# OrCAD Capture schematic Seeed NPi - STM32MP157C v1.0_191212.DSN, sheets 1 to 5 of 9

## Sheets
1 03 1000M Ethernet: size A3; rev: v1.01
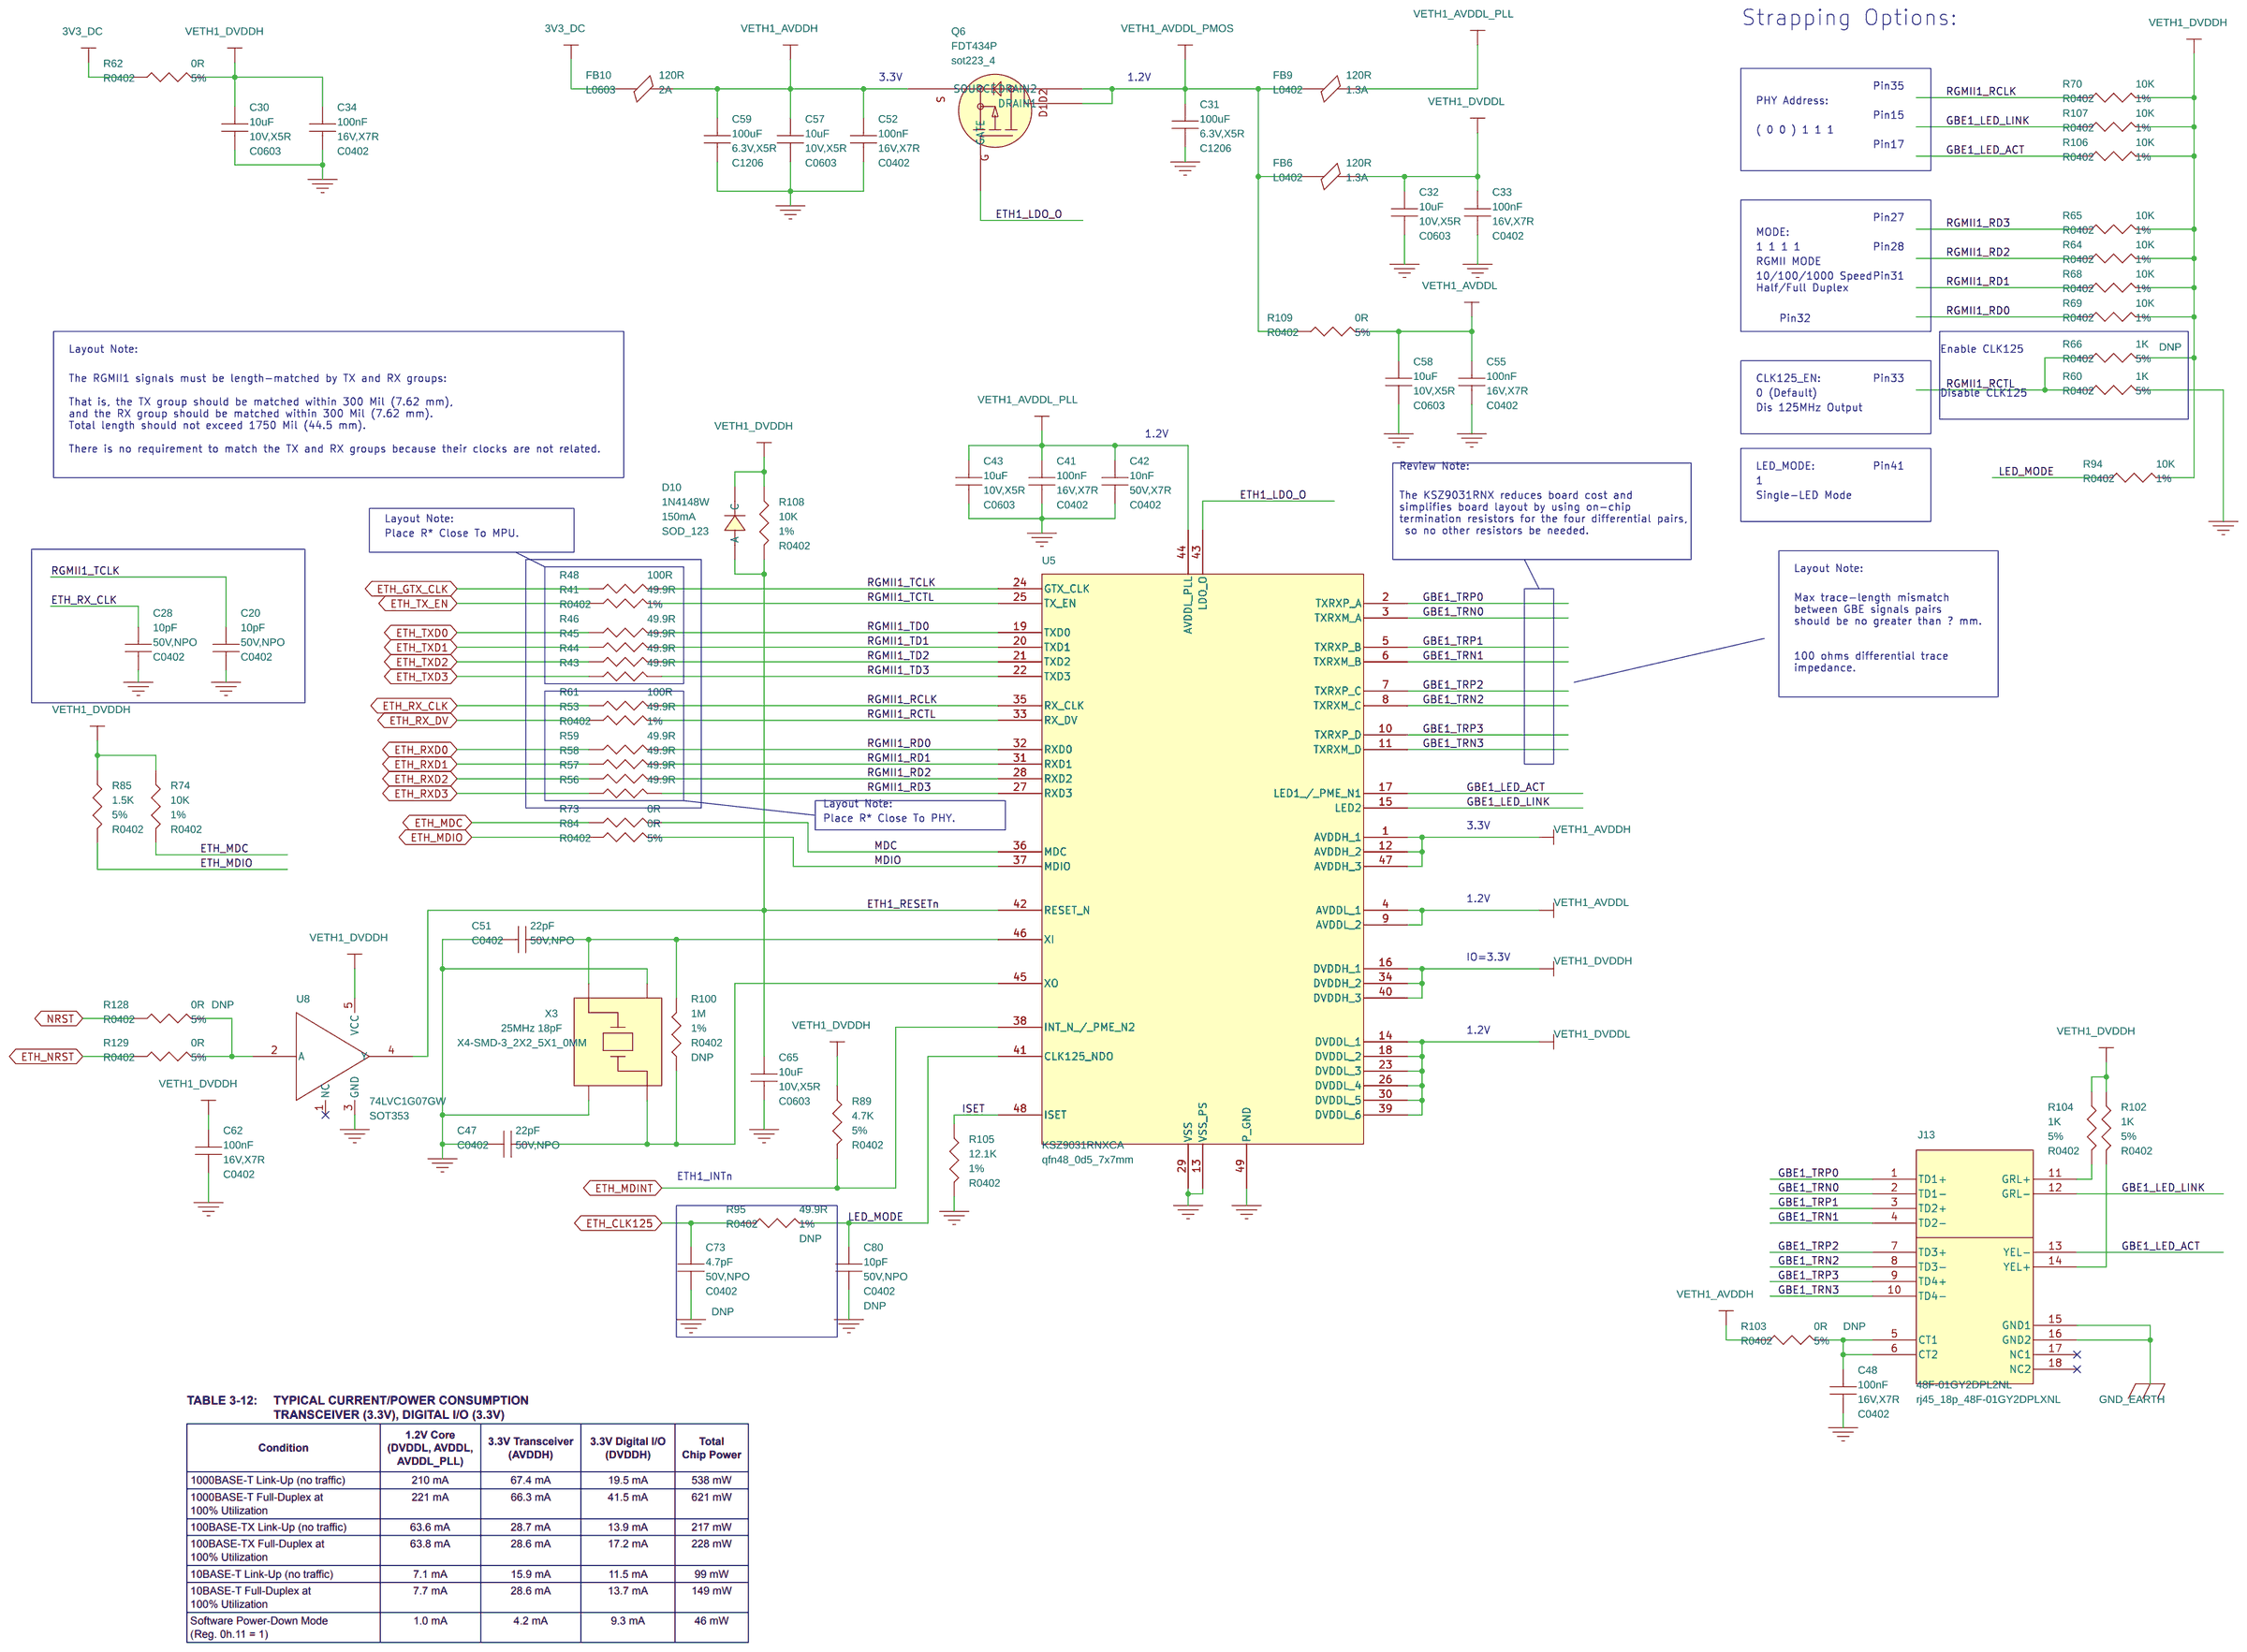
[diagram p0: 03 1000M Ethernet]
2 02 POWER: size A3
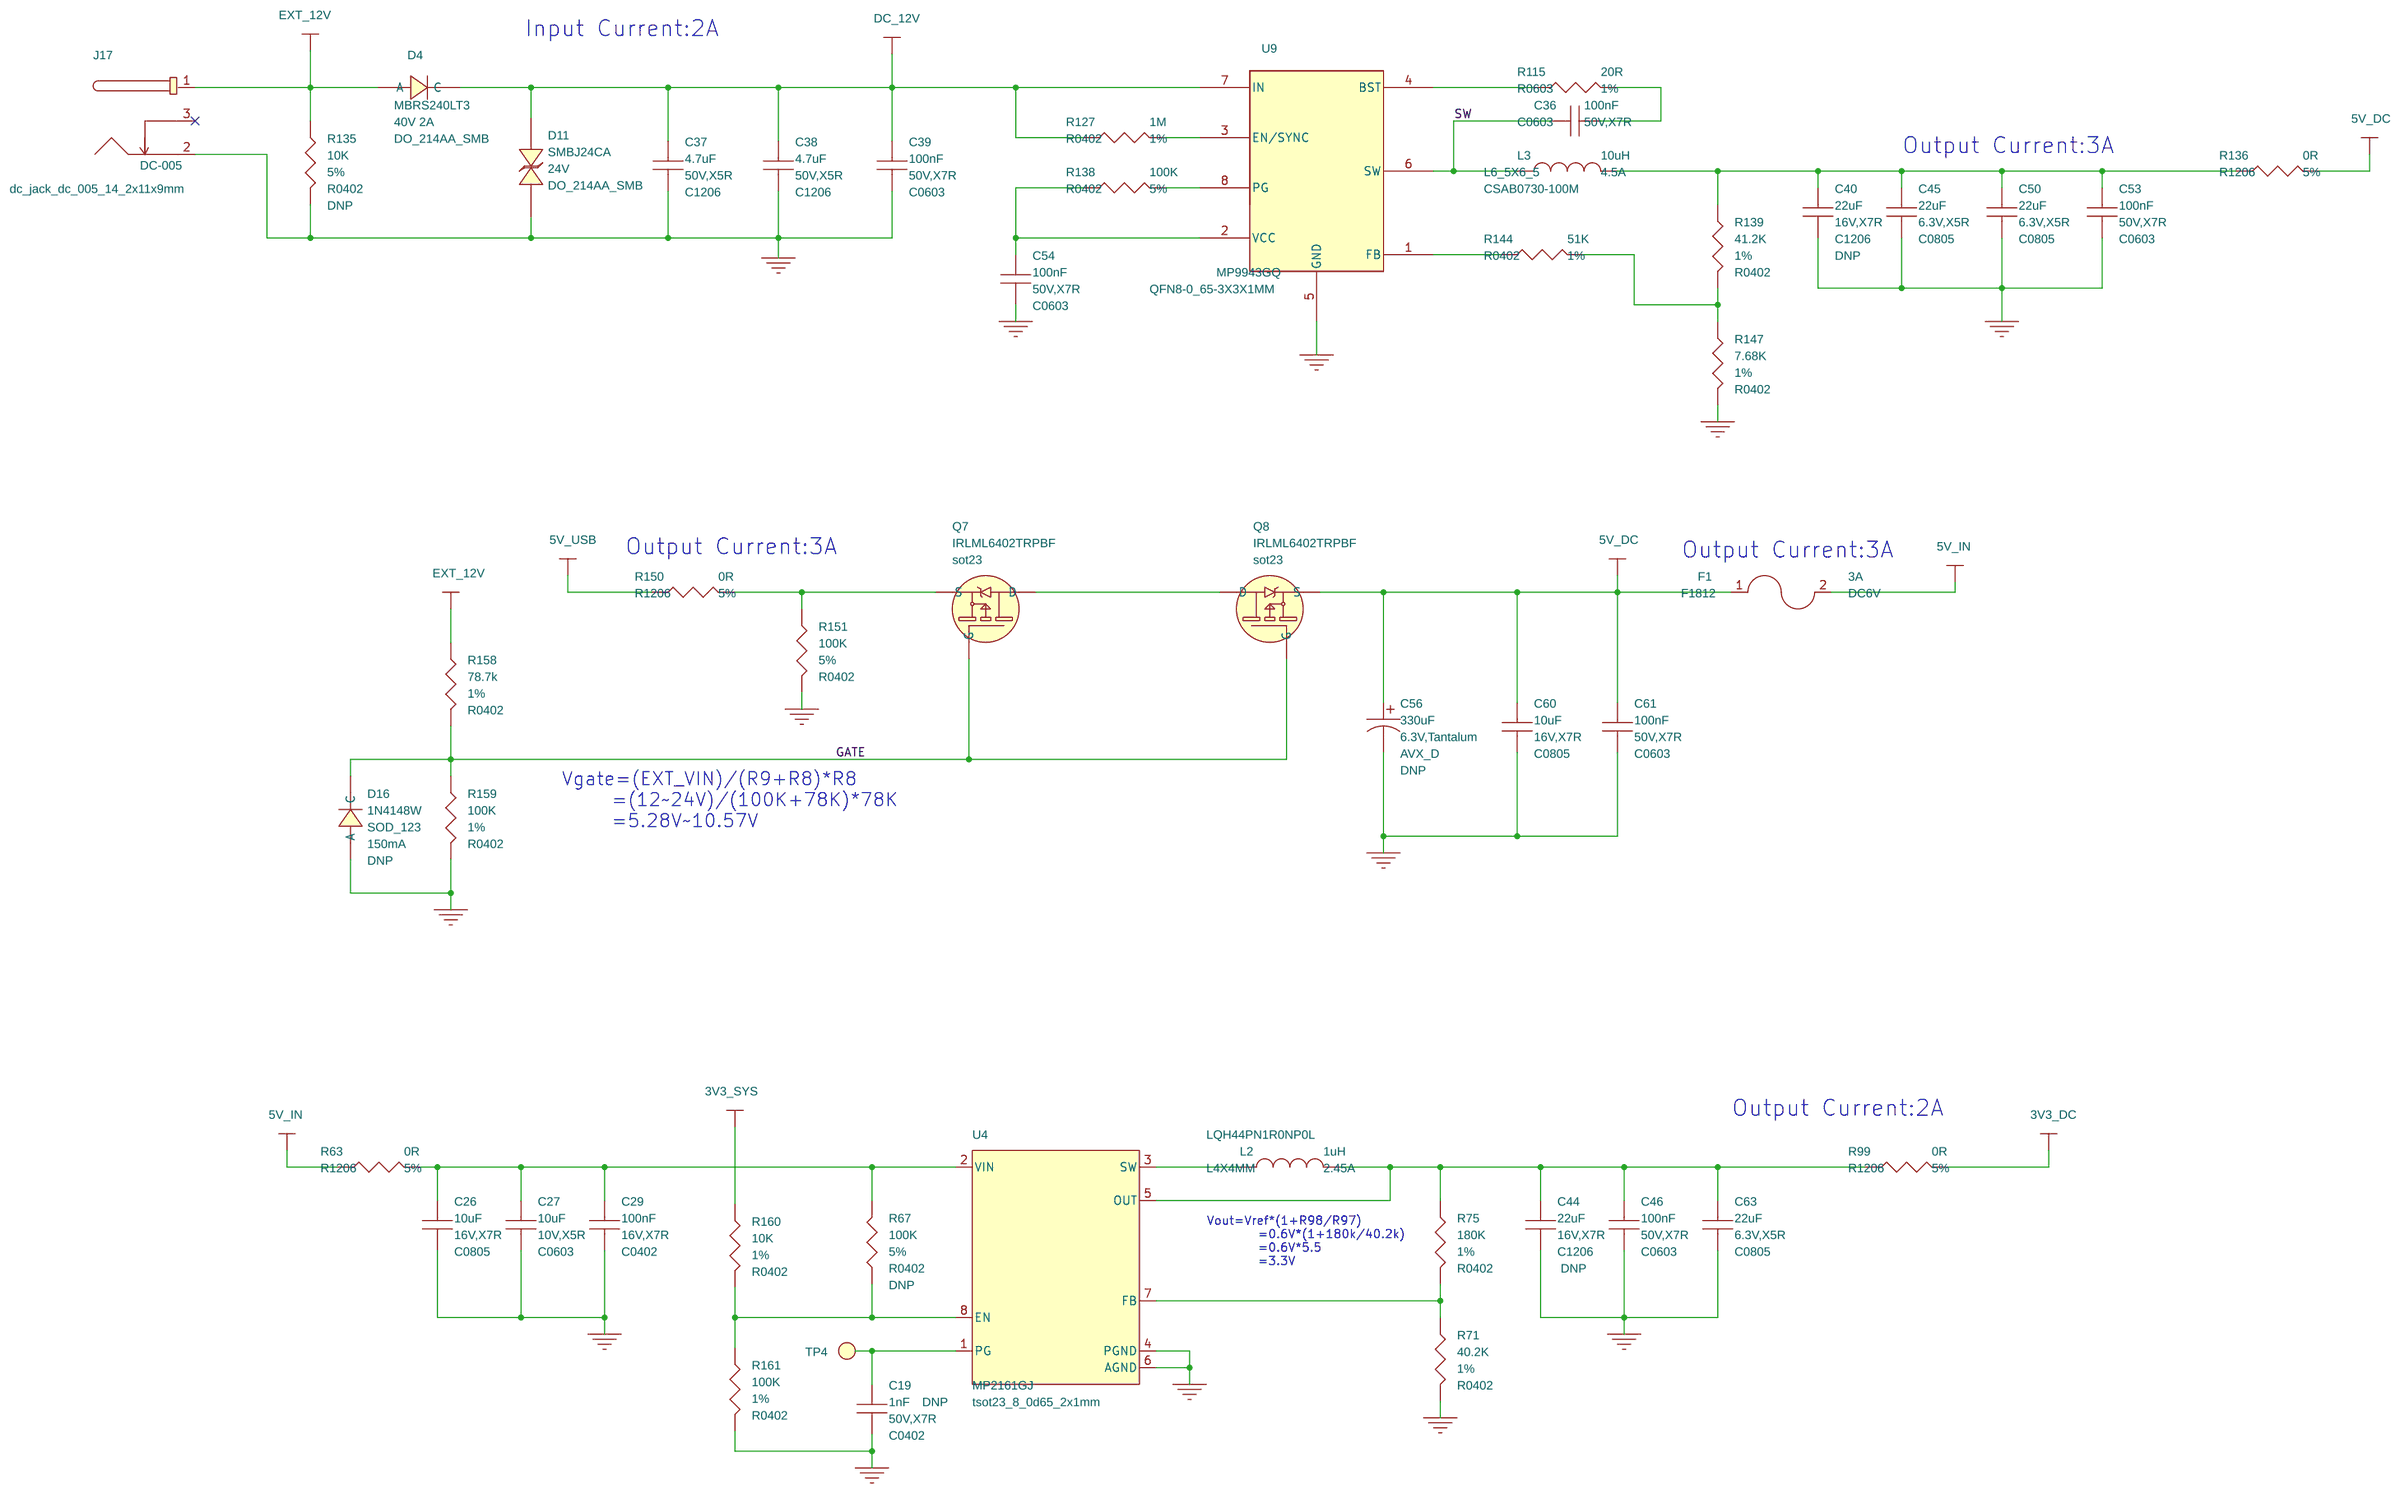
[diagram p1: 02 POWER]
3 07 PIN NAME: size A3
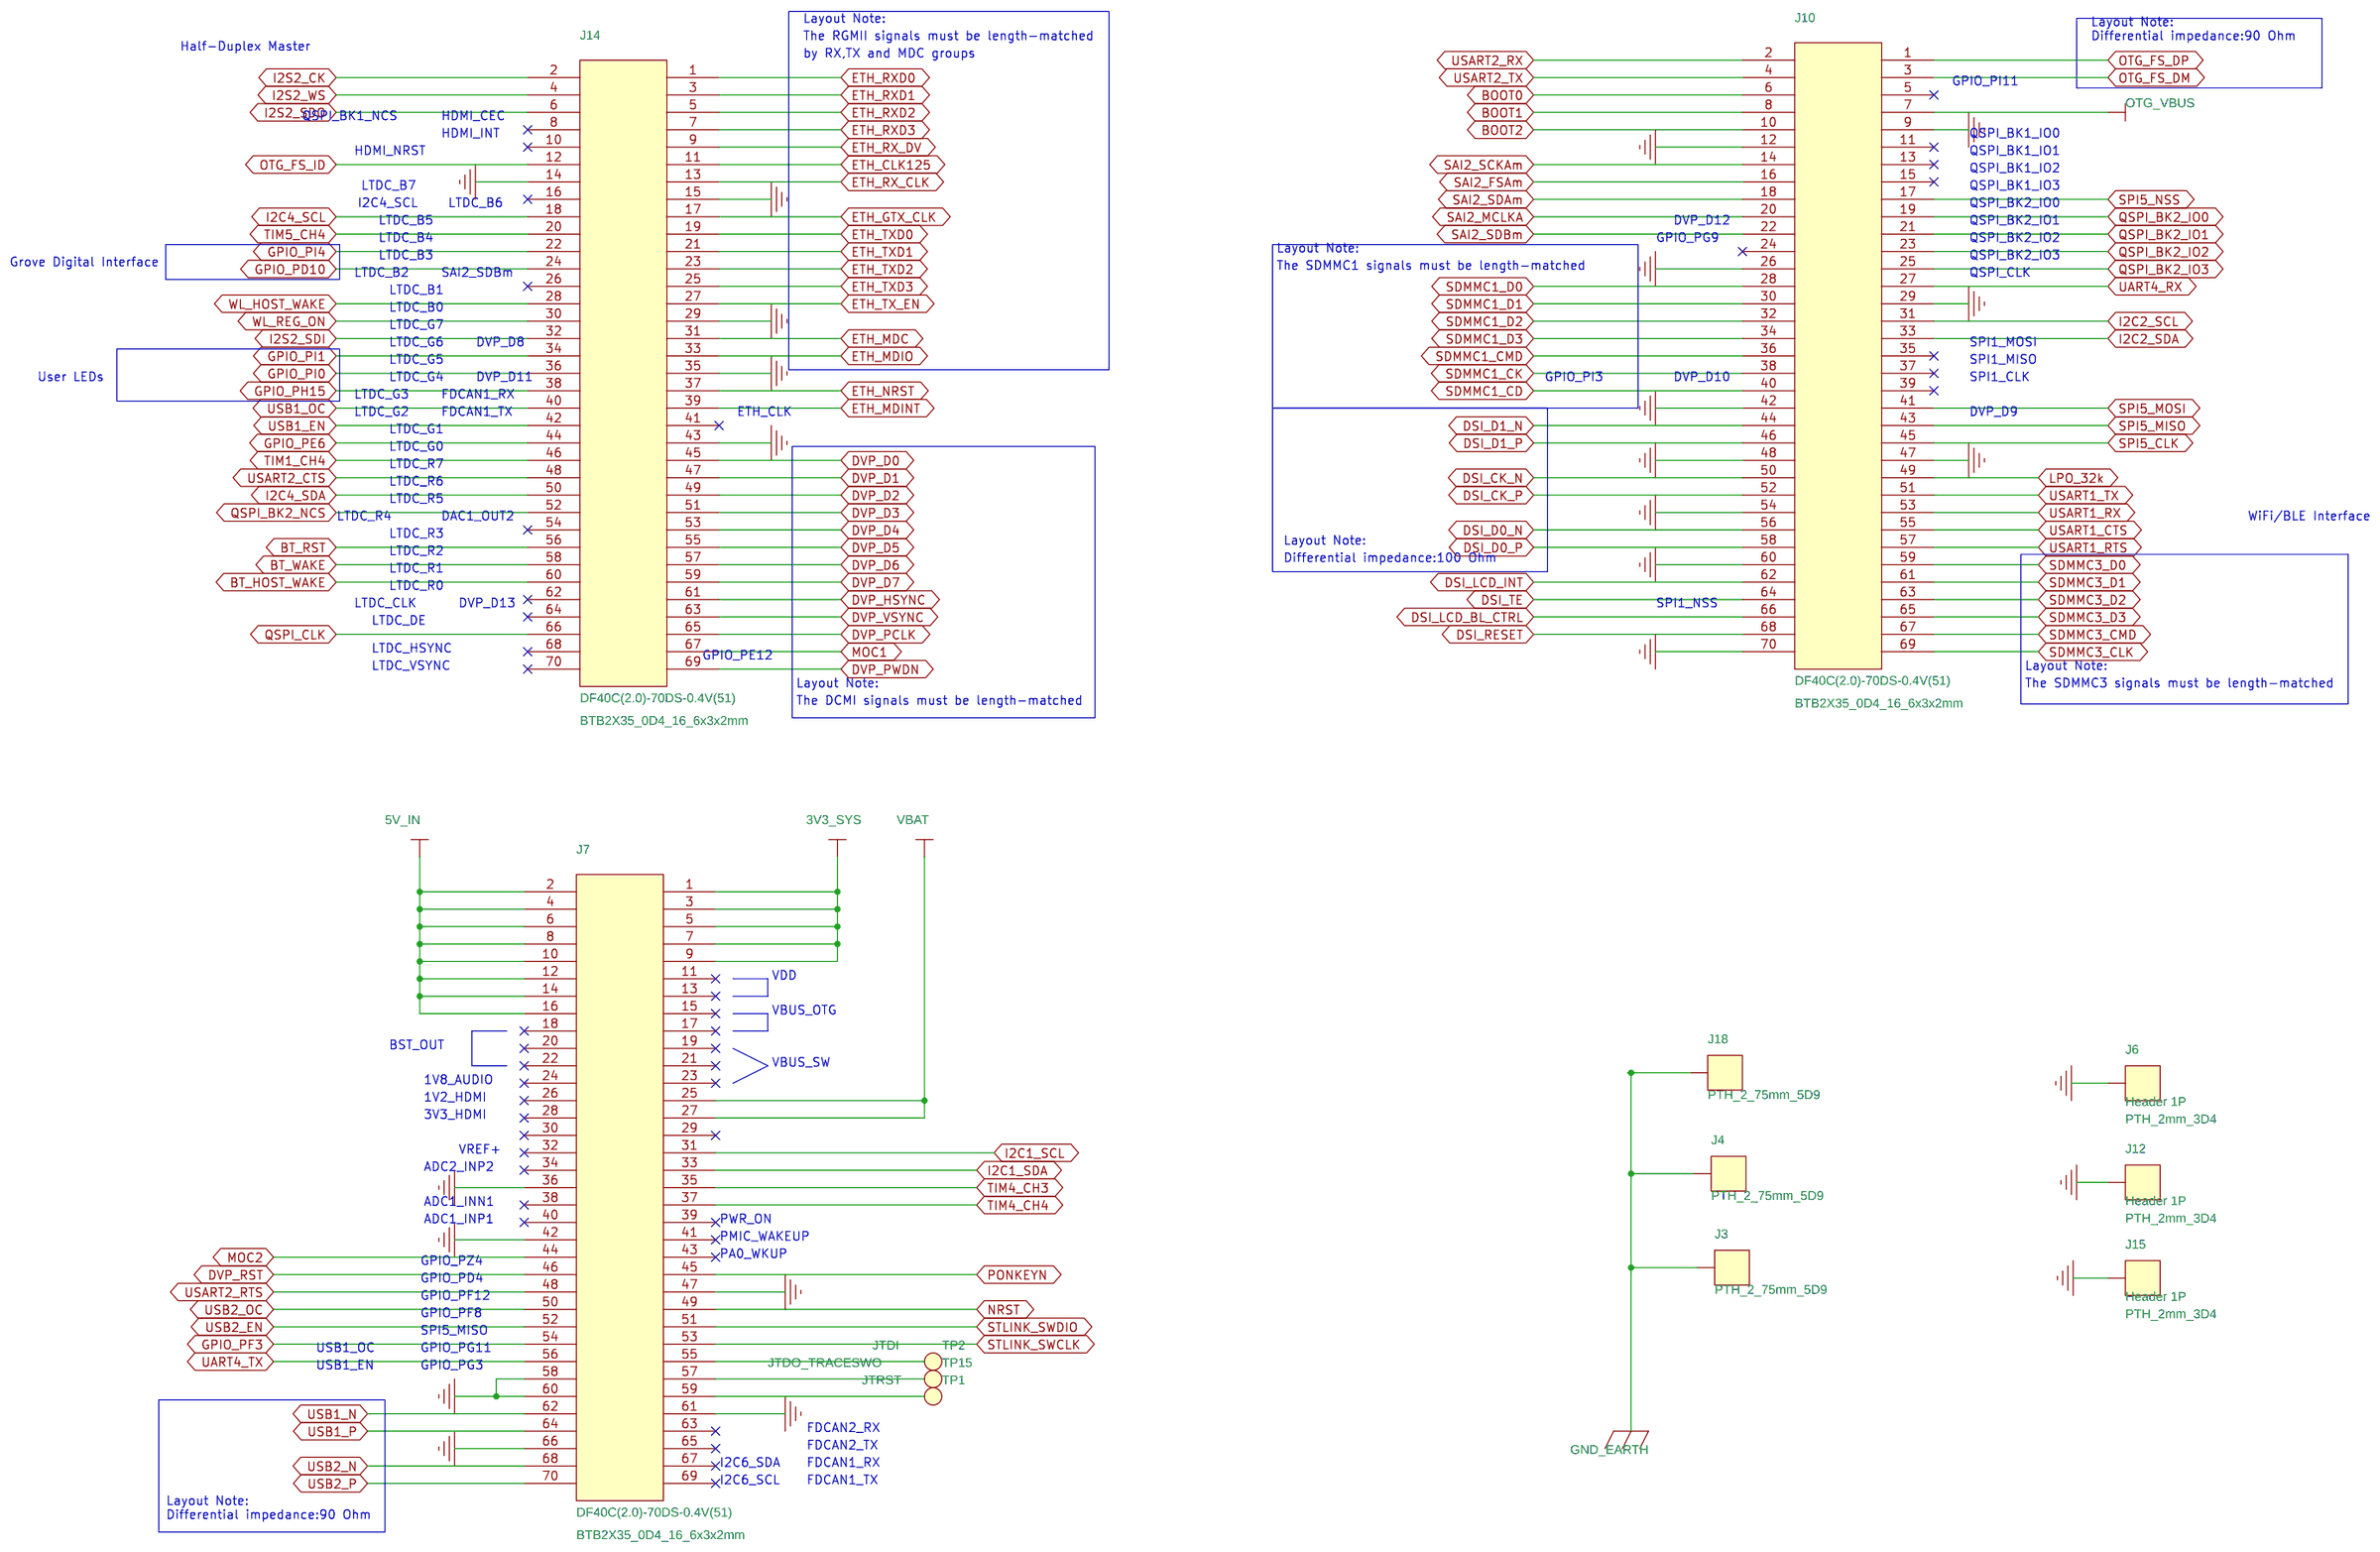
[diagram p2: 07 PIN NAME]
4 08 SD CARD/RPI: size A3
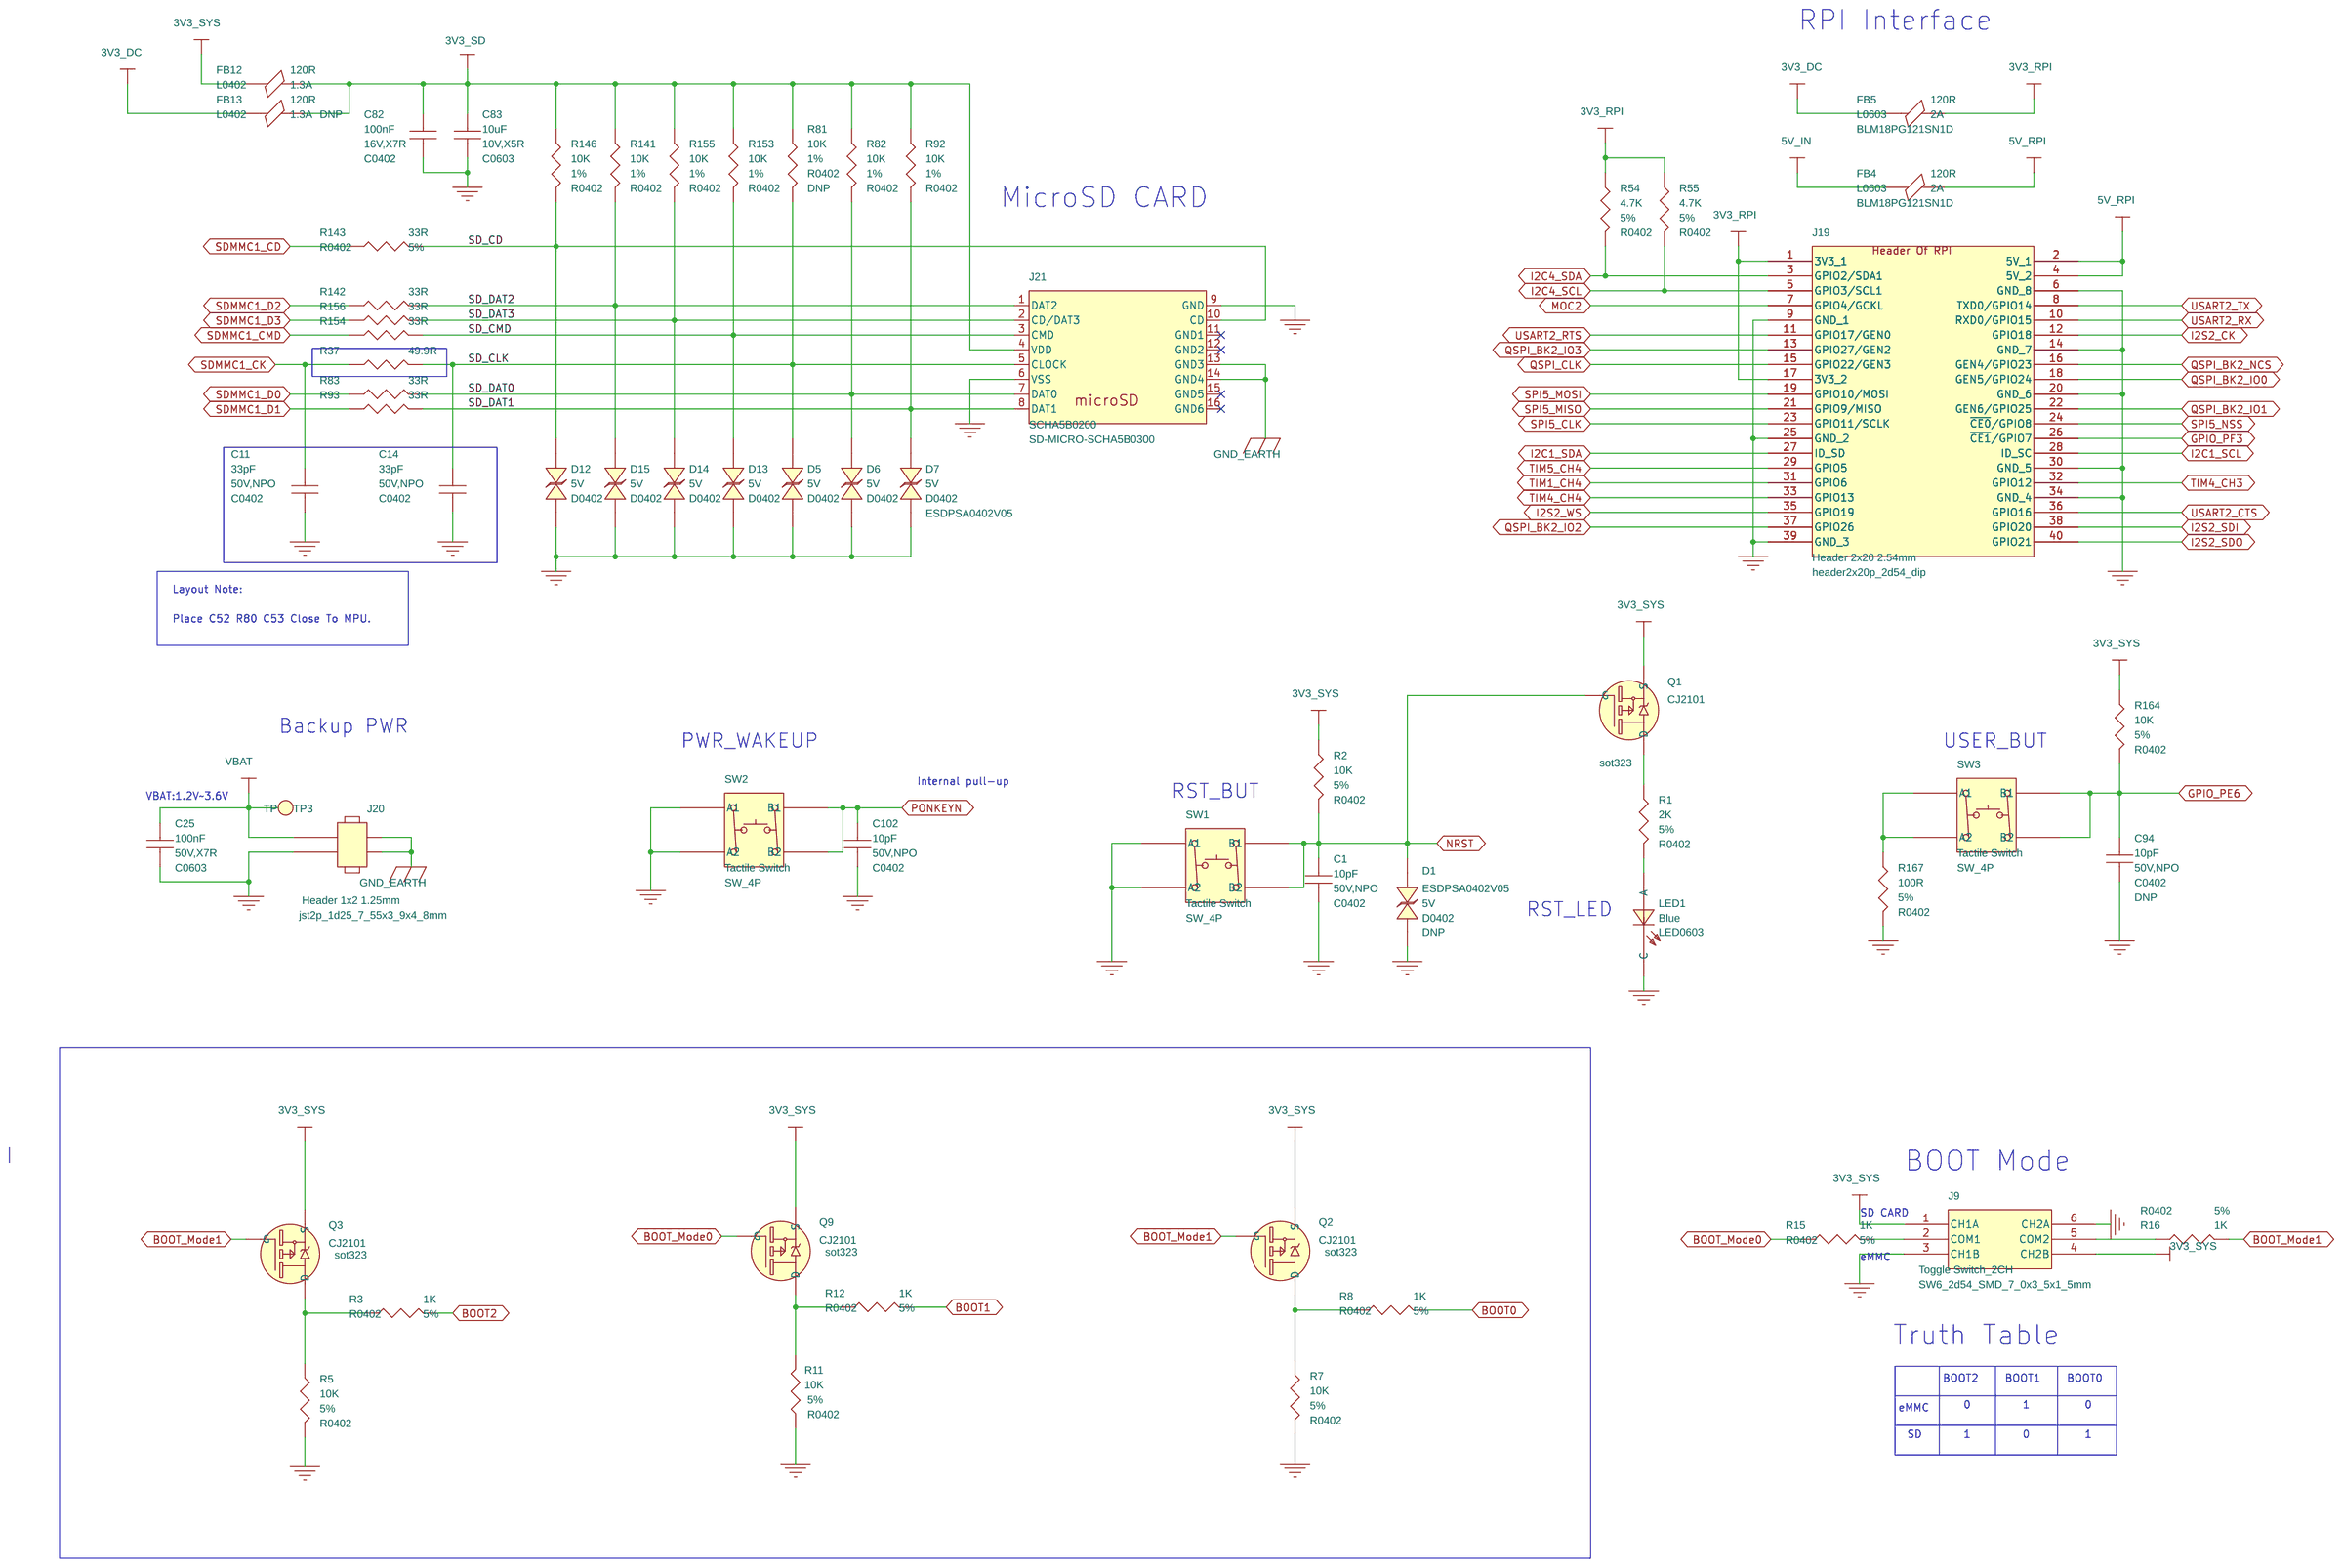
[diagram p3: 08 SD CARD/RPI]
5 06 WIFI/BLE: size A3
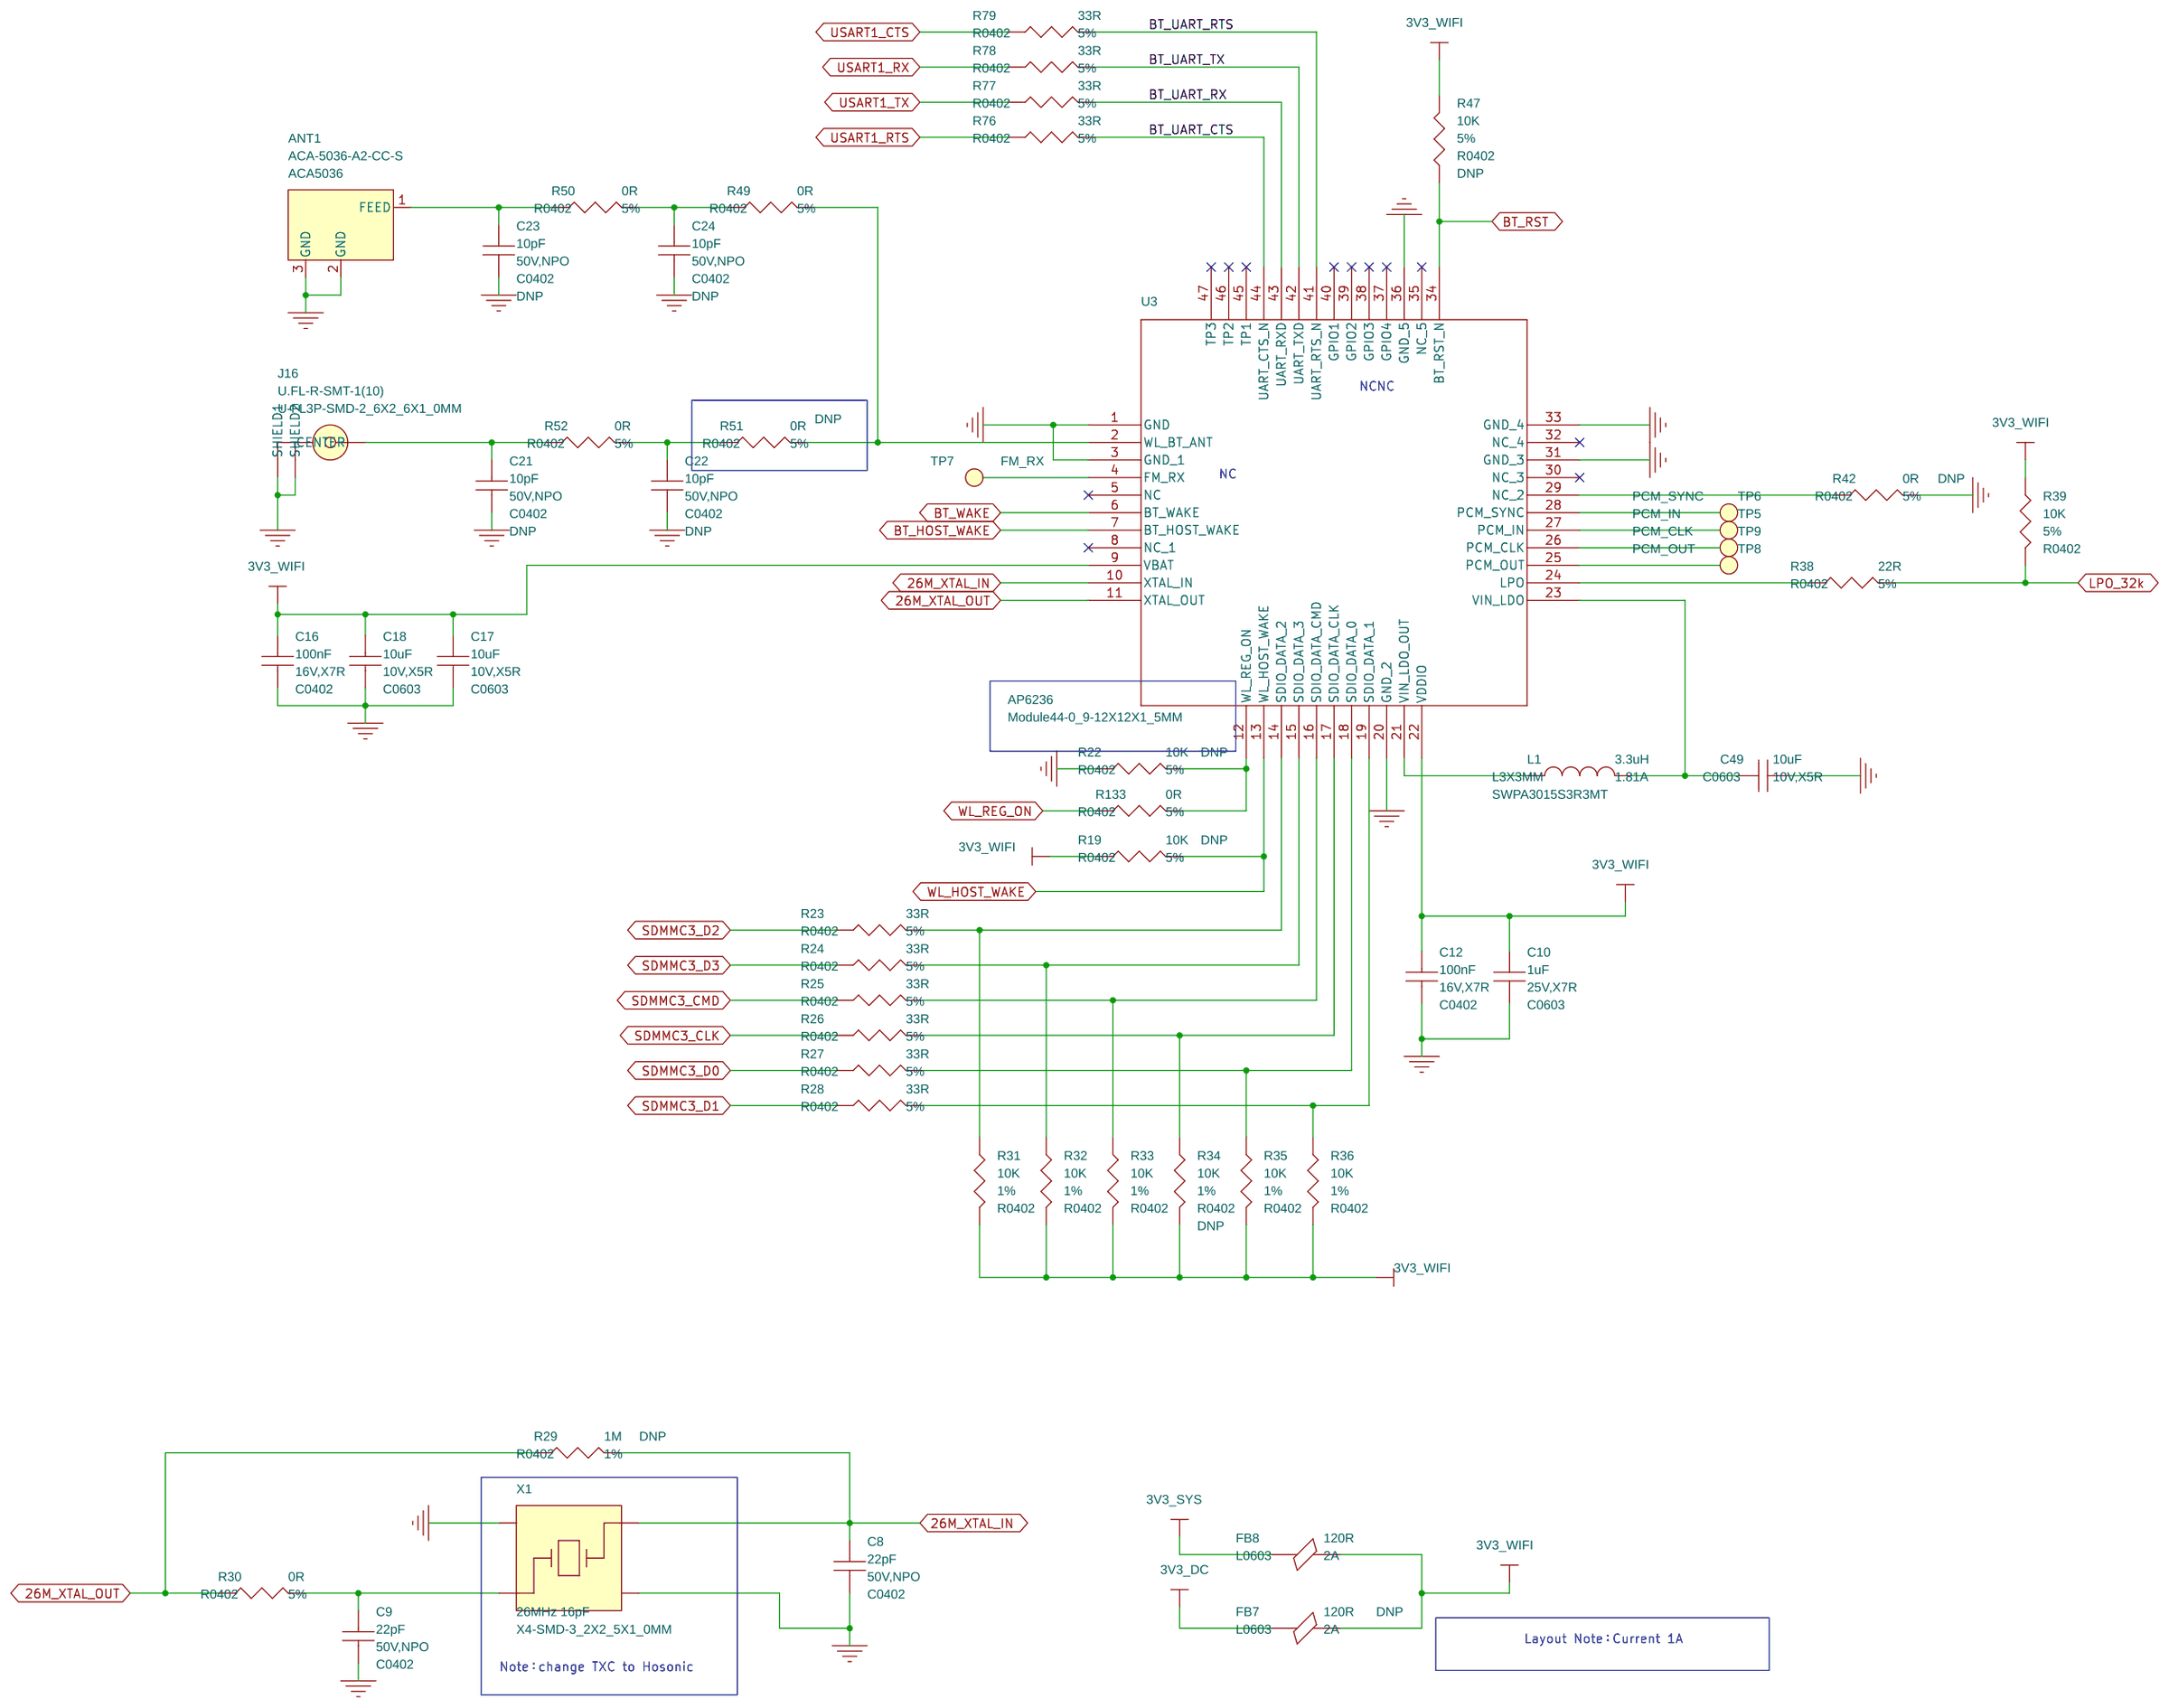
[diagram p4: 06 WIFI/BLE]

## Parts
sheet 02 POWER
C19  1nF  [C0402]
C26  10uF  [C0805]
C27  10uF  [C0603]
C29  100nF  [C0402]
C36  100nF  [C0603]
C37  4.7uF  [C1206]
C38  4.7uF  [C1206]
C39  100nF  [C0603]
C40  22uF  [C1206]
C44  22uF  [C1206]
C45  22uF  [C0805]
C46  100nF  [C0603]
C50  22uF  [C0805]
C53  100nF  [C0603]
C54  100nF  [C0603]
C56  330uF  [AVX_D]
C60  10uF  [C0805]
C61  100nF  [C0603]
C63  22uF  [C0805]
D4  MBRS240LT3  [DO_214AA_SMB]
D11  SMBJ24CA  [DO_214AA_SMB]
D16  1N4148W  [SOD_123]
F1  3A  [F1812]
J17  DC-005  [dc_jack_dc_005_14_2x11x9mm]
L2  1uH  [L4X4MM]
L3  10uH  [L6_5X6_5]
Q7  IRLML6402TRPBF  [sot23]
Q8  IRLML6402TRPBF  [sot23]
R63  0R  [R1206]
R67  100K  [R0402]
R71  40.2K  [R0402]
R75  180K  [R0402]
R99  0R  [R1206]
R115  20R  [R0603]
R127  1M  [R0402]
R135  10K  [R0402]
R136  0R  [R1206]
R138  100K  [R0402]
R139  41.2K  [R0402]
R144  51K  [R0402]
R147  7.68K  [R0402]
R150  0R  [R1206]
R151  100K  [R0402]
R158  78.7k  [R0402]
R159  100K  [R0402]
R160  10K  [R0402]
R161  100K  [R0402]
TP4  A_B_SIDE  [TP30C_SMD]
U4  MP2161GJ  [tsot23_8_0d65_2x1mm]
U9  MP9943GQ  [QFN8-0_65-3X3X1MM]
sheet 03 1000M Ethernet
C20  10pF  [C0402]
C28  10pF  [C0402]
C30  10uF  [C0603]
C31  100uF  [C1206]
C32  10uF  [C0603]
C33  100nF  [C0402]
C34  100nF  [C0402]
C41  100nF  [C0402]
C42  10nF  [C0402]
C43  10uF  [C0603]
C47  22pF  [C0402]
C48  100nF  [C0402]
C51  22pF  [C0402]
C52  100nF  [C0402]
C55  100nF  [C0402]
C57  10uF  [C0603]
C58  10uF  [C0603]
C59  100uF  [C1206]
C62  100nF  [C0402]
C65  10uF  [C0603]
C73  4.7pF  [C0402]
C80  10pF  [C0402]
D10  1N4148W  [SOD_123]
FB6  120R  [L0402]
FB9  120R  [L0402]
FB10  120R  [L0603]
J13  48F-01GY2DPL2NL  [rj45_18p_48F-01GY2DPLXNL]
Q6  FDT434P  [sot223_4]
R41  49.9R  [R0402]
R43  49.9R  [R0402]
R44  49.9R  [R0402]
R45  49.9R  [R0402]
R46  49.9R  [R0402]
R48  100R  [R0402]
R53  49.9R  [R0402]
R56  49.9R  [R0402]
R57  49.9R  [R0402]
R58  49.9R  [R0402]
R59  49.9R  [R0402]
R60  1K  [R0402]
R61  100R  [R0402]
R62  0R  [R0402]
R64  10K  [R0402]
R65  10K  [R0402]
R66  1K  [R0402]
R68  10K  [R0402]
R69  10K  [R0402]
R70  10K  [R0402]
R73  0R  [R0402]
R74  10K  [R0402]
R84  0R  [R0402]
R85  1.5K  [R0402]
R89  4.7K  [R0402]
R94  10K  [R0402]
R95  49.9R  [R0402]
R100  1M  [R0402]
R102  1K  [R0402]
R103  0R  [R0402]
R104  1K  [R0402]
R105  12.1K  [R0402]
R106  10K  [R0402]
R107  10K  [R0402]
R108  10K  [R0402]
R109  0R  [R0402]
R128  0R  [R0402]
R129  0R  [R0402]
U5  KSZ9031RNXCA  [qfn48_0d5_7x7mm]
U8  74LVC1G07GW  [SOT353]
X3  25MHz 18pF  [X4-SMD-3_2X2_5X1_0MM]
sheet 06 WIFI/BLE
ANT1  ACA-5036-A2-CC-S  [ACA5036]
C8  22pF  [C0402]
C9  22pF  [C0402]
C10  1uF  [C0603]
C12  100nF  [C0402]
C16  100nF  [C0402]
C17  10uF  [C0603]
C18  10uF  [C0603]
C21  10pF  [C0402]
C22  10pF  [C0402]
C23  10pF  [C0402]
C24  10pF  [C0402]
C49  10uF  [C0603]
FB7  120R  [L0603]
FB8  120R  [L0603]
J16  U.FL-R-SMT-1(10)  [U-FL3P-SMD-2_6X2_6X1_0MM]
L1  3.3uH  [L3X3MM]
R19  10K  [R0402]
R22  10K  [R0402]
R23  33R  [R0402]
R24  33R  [R0402]
R25  33R  [R0402]
R26  33R  [R0402]
R27  33R  [R0402]
R28  33R  [R0402]
R29  1M  [R0402]
R30  0R  [R0402]
R31  10K  [R0402]
R32  10K  [R0402]
R33  10K  [R0402]
R34  10K  [R0402]
R35  10K  [R0402]
R36  10K  [R0402]
R38  22R  [R0402]
R39  10K  [R0402]
R42  0R  [R0402]
R47  10K  [R0402]
R49  0R  [R0402]
R50  0R  [R0402]
R51  0R  [R0402]
R52  0R  [R0402]
R76  33R  [R0402]
R77  33R  [R0402]
R78  33R  [R0402]
R79  33R  [R0402]
R133  0R  [R0402]
TP5  PCM_IN  [TP30C_SMD]
TP6  PCM_SYNC  [TP30C_SMD]
TP7  FM_RX  [TP30C_SMD]
TP8  PCM_OUT  [TP30C_SMD]
TP9  PCM_CLK  [TP30C_SMD]
U3  AP6236  [Module44-0_9-12X12X1_5MM]
X1  26MHz 16pF  [X4-SMD-3_2X2_5X1_0MM]
sheet 07 PIN NAME
J3  Header_1P  [PTH_2_75mm_5D9]
J4  Header_1P  [PTH_2_75mm_5D9]
J6  Header 1P  [PTH_2mm_3D4]
J7  DF40C(2.0)-70DS-0.4V(51)  [BTB2X35_0D4_16_6x3x2mm]
J10  DF40C(2.0)-70DS-0.4V(51)  [BTB2X35_0D4_16_6x3x2mm]
J12  Header 1P  [PTH_2mm_3D4]
J14  DF40C(2.0)-70DS-0.4V(51)  [BTB2X35_0D4_16_6x3x2mm]
J15  Header 1P  [PTH_2mm_3D4]
J18  Header_1P  [PTH_2_75mm_5D9]
TP1  JTRST  [TP30C_SMD]
TP2  JTDI  [TP30C_SMD]
TP15  JTDO_TRACESWO  [TP30C_SMD]
sheet 08 SD CARD/RPI
C1  10pF  [C0402]
C11  33pF  [C0402]
C14  33pF  [C0402]
C25  100nF  [C0603]
C82  100nF  [C0402]
C83  10uF  [C0603]
C94  10pF  [C0402]
C102  10pF  [C0402]
D1  ESDPSA0402V05  [D0402]
D5  ESDPSA0402V05  [D0402]
D6  ESDPSA0402V05  [D0402]
D7  ESDPSA0402V05  [D0402]
D12  ESDPSA0402V05  [D0402]
D13  ESDPSA0402V05  [D0402]
D14  ESDPSA0402V05  [D0402]
D15  ESDPSA0402V05  [D0402]
FB4  120R  [L0603]
FB5  120R  [L0603]
FB12  120R  [L0402]
FB13  120R  [L0402]
J9  Toggle Switch_2CH  [SW6_2d54_SMD_7_0x3_5x1_5mm]
J19  Header 2x20 2.54mm  [header2x20p_2d54_dip]
J20  Header 1x2 1.25mm  [jst2p_1d25_7_55x3_9x4_8mm]
J21  SCHA5B0200  [SD-MICRO-SCHA5B0300]
LED1  Blue  [LED0603]
Q1  CJ2101  [sot323]
Q2  CJ2101  [sot323]
Q3  CJ2101  [sot323]
Q9  CJ2101  [sot323]
R1  2K  [R0402]
R2  10K  [R0402]
R3  1K  [R0402]
R5  10K  [R0402]
R7  10K  [R0402]
R8  1K  [R0402]
R11  10K  [R0402]
R12  1K  [R0402]
R15  1K  [R0402]
R16  1K  [R0402]
R37  49.9R  [R0402]
R54  4.7K  [R0402]
R55  4.7K  [R0402]
R81  10K  [R0402]
R82  10K  [R0402]
R83  33R  [R0402]
R92  10K  [R0402]
R93  33R  [R0402]
R141  10K  [R0402]
R142  33R  [R0402]
R143  33R  [R0402]
R146  10K  [R0402]
R153  10K  [R0402]
R154  33R  [R0402]
R155  10K  [R0402]
R156  33R  [R0402]
R164  10K  [R0402]
R167  100R  [R0402]
SW1  Tactile Switch  [SW_4P]
SW2  Tactile Switch  [SW_4P]
SW3  Tactile Switch  [SW_4P]
TP3  TP  [TP60C_SMD]

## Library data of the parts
C19 = CC: SMD CAP Ceramic 1nF-50V-10%-X7R;0402; ASSY: DNP; Manufacturer: YAGEO; Manufacturer Part Number: CC0402KRX7R9BB102; PN: 302010005; Part Type: Ceramic; Rating: 50V,X7R; Status: RT-M7; Temperature: -55°C to 125°C
C26 C60 = CC: SMD CAP Ceramic 10uF-16V-10%-X7R;0805; Manufacturer: YAGEO; Manufacturer Part Number: CC0805MKX7R7BB106; PN: 302011546; Part Type: Ceramic; Rating: 16V,X7R; Status: Sensecap Gateway V1; Temperature: -55°C to 125°C
C17 C18 C27 C30 C32 C43 C49 C57 C58 C65 C83 = CC: SMD CAP Ceramic 10uF-10V-10%-X5R;0603; Manufacturer: YAGEO; Manufacturer Part Number: CC0603KRX5R6BB106; PN: 302010103; Part Type: Ceramic; Rating: 10V,X5R; Status: BeagleBone Carrier Board; Temperature: -55°C to 85°C
C12 C16 C29 C33 C34 C41 C48 C52 C55 C62 C82 = CC: SMD CAP Ceramic 100nF-16V-10%-X7R;0402; Manufacturer: YAGEO; Manufacturer Part Number: CC0402KRX7R7BB104; PN: 302010004; Part Type: Ceramic; Rating: 16V,X7R; Status: BeagleBone Carrier Board; Temperature: -55°C to 125°C
C25 C36 C39 C46 C53 C54 C61 = CC: SMD CAP Ceramic 100nF-50V-10%-X7R;0603; Manufacturer: YAGEO; Manufacturer Part Number: CC0603KRX7R9BB104; PN: 302010138; Part Type: Ceramic; Rating: 50V,X7R; Status: BeagleBone Carrier Board; Temperature: -55°C to 125°C
C37 C38 = CC: SMD CAP Ceramic 4.7uF-50V-10%-X5R;1206; Manufacturer: YAGEO; Manufacturer Part Number: CC1206KKX5R9BB475; PN: 302010243; Part Type: Ceramic; Rating: 50V,X5R; Status: BeagleBone Carrier Board; Temperature: -55°C to 85°C
C40 C44 = CC: SMD CAP Ceramic 22uF-16V-10%-X7R;1206; ASSY: DNP; Manufacturer: YAGEO; Manufacturer Part Number: CC1206KKX7R7BB226; PN: 302010182; Part Type: Ceramic; Rating: 16V,X7R; Status: BeagleBone Carrier Board; Temperature: -55°C to 125°C
C45 C50 C63 = CC: SMD CAP Ceramic 22uF-6.3V-20%-X5R;0805; Manufacturer: YAGEO; Manufacturer Part Number: CC0805MKX5R5BB226; PN: 302010171; Part Type: Ceramic; Rating: 6.3V,X5R; Status: RT-M7; Temperature: -55°C to 85°C
C56 = CT: SMD CAP Tantalum 330uF-6.3V;D; ASSY: DNP; Manufacturer: KEMET; Manufacturer Part Number: T520D337M006ATE025; PN: 302020310; Part Type: Tantalum; Rating: 6.3V,Tantalum; Status: Sensecap Gateway V1
D4 = D: SMD Diode Schottky 40V-2A;SMB; Manufacturer: ON; PN: 304020025; Part Type: Diode; Rating: 40V 2A; Status: Combox Pro; Temperature: -55°C to 150°C
D11 = DIODE_TVS_BI-DIR: SMD Diode TVS 24VWM 29.5V;SMB; Manufacturer: Littelfuse; PN: 304050579; Part Type: TVS; Rating: 24V; Status: Combox Pro; Temperature: -65°C to 150°C
D16 = D: SMD Diode;100V-150mA-SOD-123; ASSY: DNP; Manufacturer: 长电; PN: 304010026; Part Type: Diode; Rating: 150mA; Status: BeagleBone Carrier Board
F1 = Fuse: SMD PPTC;3A-6V-1812; Manufacturer: DaRong; Manufacturer Part Number: SMD1812R300SF 6V 3A; PN: 307010029; Rating: DC6V; Status: ST; Temperature: - 40 °C to 85 °C
J17 = Power_Jack: DIP DC Power Jack W/P-2.0-Black;3P-L14.2*W9.0*H11.0mm-90D; Manufacturer: 百斯特; PN: 320120003; Part Type: Power Jack; Status: Seeed BeagleBone Green Gateway
L2 = L: SMD Inductor;1uH-30%-2.45A-4*4*1.8mm; Manufacturer: Murata; Manufacturer Part Number: LQH44PN1R0NP0L; PN: 303010119; Part Type: Inductor; Rating: 2.45A; Status: RT-M7; Temperature: -40°C to 125°C
L3 = L: SMD Inductor 10uH-20%;SMD-2P-L6.6*W6.6*H2.8mm; Manufacturer: CODACA; Manufacturer Part Number: CSAB0730-100M; PN: 303010016; Part Type: Inductor; Rating: 4.5A; Status: Sensecap Gateway V2; Temperature: -55°C to 125°C
Q7 Q8 = PMOS_123: SMD MOSFET P-CH 20V-3.7A;SOT-23; Manufacturer: Infineon; PN: 305031060; Part Type: PMOS; Rating: 20V 3.7A; Status: ST
R63 R99 R136 R150 = R: SMD RES 0R-5%-1/4W;1206; Manufacturer: YAGEO; Manufacturer Part Number: RC1206JR-070RL; PN: 301010407; Part Type: RES; Rating: 5%; Status: BeagleBone Carrier Board; Temperature: -55°C to 155°C
R67 = R: SMD RES 100K-5%-1/16W;0402; ASSY: DNP; Manufacturer: YAGEO; Manufacturer Part Number: RC0402JR-07100KL; PN: 301010033; Part Type: RES; Rating: 5%; Status: BeagleBone Carrier Board; Temperature: -55°C to 155°C
R71 = R: SMD RES 40.2K-1%-1/16W;0402; Manufacturer: YAGEO; Manufacturer Part Number: RC0402FR-0740K2L; PN: 301010062; Part Type: RES; Rating: 1%; Status: RT-M7; Temperature: -55°C to 155°C
R75 = R: SMD RES 180K-1%-1/16W;0402; Manufacturer: YAGEO; Manufacturer Part Number: RC0402FR-07180KL; PN: 301010814; Part Type: RES; Rating: 1%; Status: RT-M7; Temperature: -55°C to 155°C
R115 = R: SMD RES 20R-1%-1/10W;0603; Manufacturer: YAGEO; Manufacturer Part Number: RC0603FR-0720RL; PN: 301010186; Part Type: RES; Rating: 1%; Status: ST; Temperature: -55°C to 155°C
R127 = R: SMD RES 1M-1%-1/16W;0402; Manufacturer: YAGEO; Manufacturer Part Number: RC0402FR-071ML; PN: 301010043; Part Type: RES; Rating: 1%; Status: BeagleBone Carrier Board; Temperature: -55°C to 155°C
R19 R22 R47 R135 = R: SMD RES 10K-5%-1/16W;0402; ASSY: DNP; Manufacturer: YAGEO; Manufacturer Part Number: RC0402JR-0710KL; PN: 301010004; Part Type: RES; Rating: 5%; Status: BeagleBone Carrier Board; Temperature: -55°C to 155°C
R138 R151 = R: SMD RES 100K-5%-1/16W;0402; Manufacturer: YAGEO; Manufacturer Part Number: RC0402JR-07100KL; PN: 301010033; Part Type: RES; Rating: 5%; Status: BeagleBone Carrier Board; Temperature: -55°C to 155°C
R139 = R: SMD RES 41.2K-1%-1/16W;0402; Manufacturer: YAGEO; Manufacturer Part Number: RC0402FR-0741K2L; PN: 301012857; Part Type: RES; Rating: 1%; Status: ST; Temperature: -55°C to 155°C
R144 = R: SMD RES 51K-5%-1/16W;0402; Manufacturer: YAGEO; Manufacturer Part Number: RC0402JR-0751KL; PN: 301010027; Part Type: RES; Rating: 1%; Temperature: -55°C to 155°C
R147 = R: SMD RES 7.68K-1%-1/16W;0402; Manufacturer: YAGEO; Manufacturer Part Number: RC0402FR-077K68L; PN: 301012858; Part Type: RES; Rating: 1%; Status: ST; Temperature: -55°C to 155°C
R158 = R: SMD RES 78.7K-1%-1/10W;0402; Manufacturer: YAGEO; Manufacturer Part Number: RC0402FR-0778K7L; PN: 301012699; Part Type: RES; Rating: 1%; Status: ST; Temperature: -55°C to 155°C
R159 R161 = R: SMD RES 100K-1%-1/16W;0402; Manufacturer: YAGEO; Manufacturer Part Number: RC0402FR-07100KL; PN: 301010456; Part Type: RES; Rating: 1%; Status: BeagleBone Carrier Board; Temperature: -55°C to 155°C
R31-R33 R35 R36 R64 R65 R68-R70 R74 R82 R92 R94 R106-R108 R141 R146 R153 R155 R160 = R: SMD RES 10K-1%-1/16W;0402; Manufacturer: YAGEO; Manufacturer Part Number: RC0402FR-0710KL; PN: 301010047; Part Type: RES; Rating: 1%; Status: BeagleBone Carrier Board; Temperature: -55°C to 155°C
TP1-TP9 TP15 = TESTPT1
U4 = MP2161: SMD IC PMIC;DCDC Buck-ADJ-2A;TSOT23-8; Manufacturer: MPS; PN: 310031334; Part Type: DCDC; Status: RT-M7
U9 = MP9943: SMD IC PMIC;QFN-8; Manufacturer: MPS; PN: 310031860; Part Type: PMIC; Status: ST
C1 C20 C28 C102 = CC: SMD CAP Ceramic 10pF-50V-5%-NPO;0402; Manufacturer: YAGEO; Manufacturer Part Number: CC0402JRNPO9BN100; PN: 302010001; Part Type: Ceramic; Rating: 50V,NPO; Status: BeagleBone Carrier Board; Temperature: -55°C to 125°C
C31 C59 = CC: SMD CAP Ceramic 100uF-6.3V-20%-X5R;1206; Manufacturer: Murata; Manufacturer Part Number: GRM31CR60J107ME39L; PN: 302010183; Part Type: Ceramic; Rating: 6.3V,X5R; Status: BeagleBone Carrier Board; Temperature: -55°C to 85°C
C42 = CC: SMD CAP Ceramic 10nF-50V-10%-X7R;0402; Manufacturer: YAGEO; Manufacturer Part Number: CC0402KRX7R9BB103; PN: 302010006; Part Type: Ceramic; Rating: 50V,X7R; Status: BeagleBone Carrier Board; Temperature: -55°C to 125°C
C8 C9 C47 C51 = CC: SMD CAP Ceramic 22pF-50V-5%-NPO;0402; Manufacturer: YAGEO; Manufacturer Part Number: CC0402JRNPO9BN220; PN: 302010018; Part Type: Ceramic; Rating: 50V,NPO; Status: BeagleBone Carrier Board; Temperature: -55°C to 125°C
C73 = CC: SMD CAP Ceramic 4.7pF-50V-0.25pF-NPO;0402; ASSY: DNP; Manufacturer: YAGEO; Manufacturer Part Number: CC0402CRNPO9BN4R7; PN: 302010011; Part Type: Ceramic; Rating: 50V,NPO; Status: RT-M7; Temperature: -55°C to 125°C
C21-C24 C80 C94 = CC: SMD CAP Ceramic 10pF-50V-5%-NPO;0402; ASSY: DNP; Manufacturer: YAGEO; Manufacturer Part Number: CC0402JRNPO9BN100; PN: 302010001; Part Type: Ceramic; Rating: 50V,NPO; Status: BeagleBone Carrier Board; Temperature: -55°C to 125°C
D10 = D: SMD Diode;100V-150mA-SOD-123; Manufacturer: 长电; PN: 304010026; Part Type: Diode; Rating: 150mA; Status: BeagleBone Carrier Board
FB6 FB9 FB12 = FB: SMD Ferrite Bead 120R-1.3A;0402; Manufacturer: Murata; Manufacturer Part Number: BLM15PD121SN1D; PN: 303030040; Part Type: Ferrite Bead; Rating: 1.3A; Status: BeagleBone Carrier Board; Temperature: -55°C to 125°C
FB4 FB5 FB8 FB10 = FB: SMD Ferrite Bead;120R-2A;0603; Manufacturer: Murata; Manufacturer Part Number: BLM18PG121SN1D; PN: 303030024; Part Type: Ferrite Bead; Rating: 2A; Status: BeagleBone Carrier Board; Temperature: -55°C to 125°C
J13 = RJ45_18P_48F-01: DIP RJ45;14P-L21.59*W16.26*H13.84mm; Manufacturer: 元册科技; PN: 320140156; Part Type: RJ45; Status: BeagleBone Carrier Board
Q6 = PMOS_1S1G2D: SMD MOSFET P-CH -20V -6A;SOT-223; Manufacturer: ON; PN: 305030824; Part Type: PMOS; Rating: 20V 6A; Status: Seeed BeagleBone Green Gateway
R37 R41 R43-R46 R53 R56-R59 = R: SMD RES 49.9R-1%-1/16W;0402; Manufacturer: YAGEO; Manufacturer Part Number: RC0402FR-0749R9L; PN: 301010041; Part Type: RES; Rating: 1%; Status: BeagleBone Carrier Board; Temperature: -55°C to 155°C
R48 R61 = R: SMD RES 100R-1%-1/16W;0402; Manufacturer: YAGEO; Manufacturer Part Number: RC0402FR-07100RL; PN: 301010442; Part Type: RES; Rating: 1%; Status: BeagleBone Carrier Board; Temperature: -55°C to 155°C
R3 R8 R12 R15 R16 R60 R102 R104 = R: SMD RES 1K-5%-1/16W;0402; Manufacturer: YAGEO; Manufacturer Part Number: RC0402JR-071KL; PN: 301010006; Part Type: RES; Rating: 5%; Status: BeagleBone Carrier Board; Temperature: -55°C to 155°C
R30 R49 R50 R52 R62 R73 R84 R109 R129 R133 = R: SMD RES 0R-5%-1/16W;0402; Manufacturer: YAGEO; Manufacturer Part Number: RC0402JR-070RL; PN: 301010000; Part Type: RES; Rating: 5%; Status: BeagleBone Carrier Board; Temperature: -55°C to 155°C
R66 = R: SMD RES 1K-5%-1/16W;0402; ASSY: DNP; Manufacturer: YAGEO; Manufacturer Part Number: RC0402JR-071KL; PN: 301010006; Part Type: RES; Rating: 5%; Status: BeagleBone Carrier Board; Temperature: -55°C to 155°C
R85 = R: SMD RES 1.5K-5%-1/16W;0402; Manufacturer: YAGEO; Manufacturer Part Number: RC0402JR-071K5L; PN: 301010001; Part Type: RES; Rating: 5%; Status: BeagleBone Carrier Board; Temperature: -55°C to 155°C
R54 R55 R89 = R: SMD RES 4.7K-5%-1/16W;0402; Manufacturer: YAGEO; Manufacturer Part Number: RC0402JR-074K7L; PN: 301010010; Part Type: RES; Rating: 5%; Status: BeagleBone Carrier Board; Temperature: -55°C to 155°C
R95 = R: SMD RES 49.9R-1%-1/16W;0402; ASSY: DNP; Manufacturer: YAGEO; Manufacturer Part Number: RC0402FR-0749R9L; PN: 301010041; Part Type: RES; Rating: 1%; Status: BeagleBone Carrier Board; Temperature: -55°C to 155°C
R29 R100 = R: SMD RES 1M-1%-1/16W;0402; ASSY: DNP; Manufacturer: YAGEO; Manufacturer Part Number: RC0402FR-071ML; PN: 301010043; Part Type: RES; Rating: 1%; Status: BeagleBone Carrier Board; Temperature: -55°C to 155°C
R42 R51 R103 R128 = R: SMD RES 0R-5%-1/16W;0402; ASSY: DNP; Manufacturer: YAGEO; Manufacturer Part Number: RC0402JR-070RL; PN: 301010000; Part Type: RES; Rating: 5%; Status: BeagleBone Carrier Board; Temperature: -55°C to 155°C
R105 = R: SMD RES 12.1K-1%-1/16W;0402; Manufacturer: YAGEO; Manufacturer Part Number: RC0402FR-0712K1L; PN: 301011877; Part Type: RES; Rating: 1%; Status: BeagleBone Carrier Board; Temperature: -55°C to 155°C
U5 = KSZ9031RNX: SMD IC 10Base-T/100Base-TX/1000 Transceiver;QFN48; Manufacturer: Microchip; Manufacturer Part Number: KSZ9031RNXCA-TR; PN: 310070711; Part Type: Transceiver; Status: Seeed BeagleBone Green Gateway
U8 = SN74LVC1G07DCK: SMD IC Logic;TSSOP-5; Manufacturer: NXP; PN: 310050830; Part Type: Buffer; Status: ST; Temperature: -40°C to 125°C
X3 = XTAL_4P: SMD Crystal 25MHz-18pF-10ppm-60R;4P-L3.2*W2.5mm; Manufacturer: TXC; Manufacturer Part Number: 7M25000014; PN: 306010963; Part Type: Crystal; Rating: 10ppm; Status: ST; Temperature: -40°C to 85°C
ANT1 = Built-in_ANT_3P: SMD Built-in Antenna 2.4GHz;3P-5.2*3.7*0.7mm; Manufacturer: Inpad; PN: 318010123; Part Type: Antenna; Rating: 2.4GHz; Status: BeagleBone Green Gateway
C10 = CC: SMD CAP Ceramic 1uF-25V-10%-X7R;0603; Manufacturer: YAGEO; Manufacturer Part Number: CC0603KRX7R8BB105; PN: 302010139; Part Type: Ceramic; Rating: 25V,X7R; Status: BeagleBone Carrier Board; Temperature: -55°C to 125°C
FB7 = FB: SMD Ferrite Bead;120R-2A;0603; ASSY: DNP; Manufacturer: Murata; Manufacturer Part Number: BLM18PG121SN1D; PN: 303030024; Part Type: Ferrite Bead; Rating: 2A; Status: BeagleBone Carrier Board; Temperature: -55°C to 125°C
J16 = RF_ANT_3P: SMD U-FL Female CONN-Gold;3P-L2.6*W2.6*H1.25mm; Manufacturer: HRS; Manufacturer Part Number: U.FL-R-SMT-1(10）; PN: 320111077; Part Type: RF Connector; Status: Seeed BeagleBone Green Gateway
L1 = L: SMD Inductor 3.3uH-20%-1.81A;2P-L3.0*W3.0*H1.5mm; Manufacturer: Sunlord; Manufacturer Part Number: SWPA3015S3R3MT; PN: 303010742; Part Type: Inductor; Rating: 1.81A; Status: ST; Temperature: -40℃ to 125℃
R23-R28 R76-R79 R83 R93 R142 R143 R154 R156 = R: SMD RES 33R-5%-1/16W;0402; Manufacturer: YAGEO; Manufacturer Part Number: RC0402JR-0733RL; PN: 301010034; Part Type: RES; Rating: 5%; Status: BeagleBone Carrier Board; Temperature: -55°C to 155°C
R34 R81 = R: SMD RES 10K-1%-1/16W;0402; ASSY: DNP; Manufacturer: YAGEO; Manufacturer Part Number: RC0402FR-0710KL; PN: 301010047; Part Type: RES; Rating: 1%; Status: BeagleBone Carrier Board; Temperature: -55°C to 155°C
R38 = R: SMD RES 22R-5%-1/16W;0402; Manufacturer: YAGEO; Manufacturer Part Number: RC0402JR-0722RL; PN: 301010002; Part Type: RES; Rating: 5%; Status: BeagleBone Carrier Board; Temperature: -55°C to 155°C
R2 R5 R7 R11 R39 R164 = R: SMD RES 10K-5%-1/16W;0402; Manufacturer: YAGEO; Manufacturer Part Number: RC0402JR-0710KL; PN: 301010004; Part Type: RES; Rating: 5%; Status: BeagleBone Carrier Board; Temperature: -55°C to 155°C
U3 = Module-WIFI_AP6212: SMD Wifi Module;44P-L12*W12*H1.5mm; Manufacturer: Ampak; PN: 317060422; Part Type: BT_WIFI; Rating: -30°C~85°C; Status: ST; Temperature: -30°C to 85°C
X1 = XTAL_4P: SMD Crystal 26MHz-16pF-10ppm-50R;4P-L3.2*W2.5mm; Manufacturer: Hosonic; Manufacturer Part Number: E3SB26.0000F16G11; PN: 306010984; Part Type: Crystal; Rating: 10ppm; Status: ST; Temperature: -30°C to 85°C
J3 J4 J18 = Header_1P: Part Type: Locating hole; Status: ST
J6 J12 J15 = Header_1P: Part Type: Locating hole; Rating: 2MM_PTH定位孔; Status: ST
J7 J10 J14 = Header_2x35: SMD BTB CONN;70P-16.64*3.38*3.12mm; Manufacturer: HRS; PN: 320210002; Part Type: BTB Connector; Status: ST
C11 C14 = CC: SMD CAP Ceramic 33pF-50V-5%-NPO;0402; Manufacturer: YAGEO; Manufacturer Part Number: CC0402JRNPO9BN330; PN: 302010000; Part Type: Ceramic; Rating: 50V,NPO; Status: Mini-Gateway; Temperature: -55°C to 125°C
D1 = DIODE_TVS_BI-DIR: SMD Diode ESD 0.05pF;0402; ASSY: DNP; Manufacturer: SEMITEL; PN: 304060074; Part Type: TVS; Rating: 5V; Status: BeagleBone Carrier Board; Temperature: -40°C to 90°C
D5-D7 D12-D15 = DIODE_TVS_BI-DIR: SMD Diode ESD 0.05pF;0402; Manufacturer: SEMITEL; PN: 304060074; Part Type: TVS; Rating: 5V; Status: BeagleBone Carrier Board; Temperature: -40°C to 90°C
FB13 = FB: SMD Ferrite Bead 120R-1.3A;0402; ASSY: DNP; Manufacturer: Murata; Manufacturer Part Number: BLM15PD121SN1D; PN: 303030040; Part Type: Ferrite Bead; Rating: 1.3A; Status: BeagleBone Carrier Board; Temperature: -55°C to 125°C
J9 = Toggle_Switch_2CH: SMD Top Toggle Switch DPDT;6P-2.54-L7.0*W3.5*H1.5mm; Manufacturer: 德艺隆; Manufacturer Part Number: MS-22C01 G1.5; PN: 311030005; Part Type: Toggle Switch; Status: Grove AI HAT for Edge Computing
J19 = Header_2X20_Of_RPI: DIP Black Male Header VERT;2*20P-2.54-2.54-11.6/3.0mm; Manufacturer: 思拓展; Manufacturer Part Number: PF-3940; PN: 320020197_1; Part Type: Header; Status: ST
J20 = Header_2+2P: SMD Male CONN Header;2P-1.25mm-立贴; Manufacturer: 思拓展; Manufacturer Part Number: WY-3315; PN: 320111167; Part Type: Header; Status: SeeedStudio BeagleBone Green Gateway Baseboard; Temperature: -25°C to 85°C
J21 = MicroSD_Card_8P: SMD Micro SD Card Holder;8P-13.9*15mm; Manufacturer: ALPS; PN: 320090010; Part Type: SD Card; Status: BeagleBone Carrier Board
LED1 = Single_LED: SMD LED Clear-Blue;0603; Manufacturer: Everlight; Manufacturer Part Number: 19-217/BHC-ZL1M2RY/3T; PN: 304090045; Part Type: LED; Status: BeagleBone Carrier Board
Q1-Q3 Q9 = PMOS_123: SMD MOSFET P-CH 20V-2.1A;SOT-323; Manufacturer: 长电; PN: 305030084; Part Type: PMOS; Rating: 20V 1.4A; Status: ST
R1 = R: SMD RES 2K-5%-1/16W;0402; Manufacturer: YAGEO; Manufacturer Part Number: RC0402JR-072KL; PN: 301010065; Part Type: RES; Rating: 5%; Status: Grove AI HAT for Edge Computing; Temperature: -55°C to 155°C
R167 = R: SMD RES 100R-5%-1/16W;0402; Manufacturer: YAGEO; Manufacturer Part Number: RC0402JR-07100RL; PN: 301010028; Part Type: RES; Rating: 5%; Status: BeagleBone Carrier Board; Temperature: -55°C to 155°C
SW1 = Tactile_Switch_4P: SMD Top Button 4N;4P-L4.6*W3.2*H2.5mm; Manufacturer: ALPS; Manufacturer Part Number: SKRPADE010; PN: 311020009; Status: Seeed BeagleBone Green Gateway
SW2 SW3 = Tactile_Switch_4P: SMD Top Button 1.57N;4P-L4.6*W3.2*H2.5mm; Manufacturer: ALPS; Manufacturer Part Number: SKRPABE010; PN: 311020518; Status: BeagleBone Carrier Board

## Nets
3V3_DC: FB5.1 FB7.1 FB10.1 FB13.1 R62.1 R99.2 ; also on sheet 8 9
3V3_RPI: FB5.2 J19.1(3V3) J19.17(3V3_2) R54.1 R55.1
3V3_SD: C82.1 C83.1 FB12.2 FB13.2 J21.4(VDD) R81.1 R82.1 R92.1 R141.1 R146.1 R153.1 R155.1
3V3_SYS: FB8.1 FB12.1 J7.1 J7.3 J7.5 J7.7 J7.9 J9.1(CH1A) J9.4(CH2B) Q1.2(S) Q2.2(S) Q3.2(S) Q9.2(S) R2.1 R160.1 R164.1 ; also on sheet 6 8 9
3V3_WIFI: C10.1 C12.1 C16.1 C17.1 C18.1 FB7.2 FB8.2 R19.1 R31.2 R32.2 R33.2 R34.2 R35.2 R36.2 R39.1 R47.2 U3.9(VBAT) U3.22(VDDIO)
5V_DC: C56.1 C60.1 C61.1 F1.1 Q8.2(S) R136.2
5V_IN: F1.2 FB4.1 J7.2 J7.4 J7.6 J7.8 J7.10 J7.12 J7.14 J7.16 R63.1 ; also on sheet 6 9
5V_RPI: FB4.2 J19.2(5V_1) J19.4(5V_2)
5V_USB: R150.1 ; also on sheet 6
GND: ANT1.2(GND) ANT1.3(GND) C1.2 C8.2 C9.2 C10.2 C11.2 C12.2 C14.2 C16.2 C17.2 C18.2 C19.2 C20.2 C21.2 C22.2 C23.2 C24.2 C25.2 C26.2 C27.2 C28.2 C29.2 C30.2 C31.2 C32.2 C33.2 C34.2 C37.2 C38.2 C39.2 C40.2 C41.2 C42.2 C43.2 C44.2 C45.2 C46.2 C47.1 C48.2 C49.2 C50.2 C51.1 C52.2 C53.2 C54.2 C55.2 C56.2 C57.2 C58.2 C59.2 C60.2 C61.2 C62.2 C63.2 C65.2 C73.2 C80.2 C82.2 C83.2 C94.2 C102.2 D1.2 D5.2 D6.2 D7.2 D11.1 D12.2 D13.2 D14.2 D15.2 D16.1(A) J6.1 J7.36 J7.42 J7.47 J7.58 J7.60 J7.61 J7.66 J9.3(CH1B) J9.6(CH2A) J10.9 J10.12 J10.26 J10.29 J10.42 J10.47 J10.48 J10.54 J10.60 J10.70 J12.1 J14.14 J14.15 J14.29 J14.35 J14.43 J15.1 J16.2(SHIELD1) J16.3(SHIELD2) J17.2 J19.6(GND_8) J19.9(GND_1) J19.14(GND_7) J19.20(GND_6) J19.25(GND_2) J19.30(GND_5) J19.34(GND_4) J19.39(GND_3) J20.2 J21.6(VSS) J21.9(GND) LED1.2(C) R5.2 R7.2 R11.1 R22.1 R42.2 R60.2 R71.2 R105.2 R135.2 R147.2 R151.2 R159.2 R161.2 R167.2 SW1.1(A1) SW1.3(A2) SW2.1(A1) SW2.3(A2) U3.1(GND) U3.3(GND_1) U3.20(GND_2) U3.31(GND_3) U3.33(GND_4) U3.36(GND_5) U4.4(PGND) U4.6(AGND) U5.13(VSS_PS) U5.29(VSS) U5.49(P_GND) U8.3(GND) U9.5(GND) X1.2 X1.4 X3.2 X3.4 ; also on sheet 6 8 9
GND_EARTH: J3.1 J4.1 J13.15(GND1) J13.16(GND2) J18.1 J20.3 J20.4 J21.13(GND3) J21.14(GND4) ; also on sheet 6 8
VBAT: C25.1 J7.25 J7.27 J20.1 TP3.1(TP)
26M_XTAL_IN: C8.1 R29.2 U3.10(XTAL_IN) X1.3
26M_XTAL_OUT: R29.1 R30.1 U3.11(XTAL_OUT)
BOOT0: J10.6 R8.2
BOOT1: J10.8 R12.2
BOOT2: J10.10 R3.2
BOOT_Mode0: Q9.1(G) R15.1
BOOT_Mode1: Q2.1(G) Q3.1(G) R16.2
BT_HOST_WAKE: J14.60 U3.7(BT_HOST_WAKE)
BT_RST: J14.56 R47.1 U3.34(BT_RST_N)
BT_UART_CTS: R76.2 U3.44(UART_CTS_N)
BT_UART_RTS: R79.2 U3.41(UART_RTS_N)
BT_UART_RX: R77.2 U3.43(UART_RXD)
BT_UART_TX: R78.2 U3.42(UART_TXD)
BT_WAKE: J14.58 U3.6(BT_WAKE)
DC_12V: C37.1 C38.1 C39.1 D4.2(C) D11.2 R127.1 U9.7(IN)
DSI_CK_N: J10.50 ; also on sheet 9
DSI_CK_P: J10.52 ; also on sheet 9
DSI_D0_N: J10.56 ; also on sheet 9
DSI_D0_P: J10.58 ; also on sheet 9
DSI_D1_N: J10.44 ; also on sheet 9
DSI_D1_P: J10.46 ; also on sheet 9
DSI_LCD_BL_CTRL: J10.66 ; also on sheet 9
DSI_LCD_INT: J10.62 ; also on sheet 9
DSI_RESET: J10.68 ; also on sheet 9
DSI_TE: J10.64 ; also on sheet 9
DVP_D0: J14.45 ; also on sheet 9
DVP_D1: J14.47 ; also on sheet 9
DVP_D2: J14.49 ; also on sheet 9
DVP_D3: J14.51 ; also on sheet 9
DVP_D4: J14.53 ; also on sheet 9
DVP_D5: J14.55 ; also on sheet 9
DVP_D6: J14.57 ; also on sheet 9
DVP_D7: J14.59 ; also on sheet 9
DVP_HSYNC: J14.61 ; also on sheet 9
DVP_PCLK: J14.65 ; also on sheet 9
DVP_PWDN: J14.69 ; also on sheet 9
DVP_RST: J7.46 ; also on sheet 9
DVP_VSYNC: J14.63 ; also on sheet 9
ETH1_LDO_O: Q6.1(GATE) U5.43(LDO_O)
ETH1_RESETn: C65.1 D10.1(A) R108.2 U5.42(RESET_N) U8.4(Y)
ETH_CLK125: C73.1 J14.11 R95.1
ETH_GTX_CLK: J14.17 R48.1
ETH_MDC: J14.31 R73.1 R74.2
ETH_MDINT: J14.39 R89.2 U5.38(INT_N_/_PME_N2)
ETH_MDIO: J14.33 R84.1 R85.2
ETH_NRST: J14.37 R129.1
ETH_RX_CLK: C28.1 J14.13 R61.1
ETH_RX_DV: J14.9 R53.1
ETH_RXD0: J14.1 R59.1
ETH_RXD1: J14.3 R58.1
ETH_RXD2: J14.5 R57.1
ETH_RXD3: J14.7 R56.1
ETH_TX_EN: J14.27 R41.1
ETH_TXD0: J14.19 R46.1
ETH_TXD1: J14.21 R45.1
ETH_TXD2: J14.23 R44.1
ETH_TXD3: J14.25 R43.1
EXT_12V: D4.1(A) J17.1 R135.1 R158.1
GATE: D16.2(C) Q7.1(G) Q8.1(G) R158.2 R159.1
GBE1_LED_ACT: J13.13(YEL-) R106.1 U5.17(LED1_/_PME_N1)
GBE1_LED_LINK: J13.12(GRL-) R107.1 U5.15(LED2)
GBE1_TRN0: J13.2(TD1-) U5.3(TXRXM_A)
GBE1_TRN1: J13.4(TD2-) U5.6(TXRXM_B)
GBE1_TRN2: J13.8(TD3-) U5.8(TXRXM_C)
GBE1_TRN3: J13.10(TD4-) U5.11(TXRXM_D)
GBE1_TRP0: J13.1(TD1+) U5.2(TXRXP_A)
GBE1_TRP1: J13.3(TD2+) U5.5(TXRXP_B)
GBE1_TRP2: J13.7(TD3+) U5.7(TXRXP_C)
GBE1_TRP3: J13.9(TD4+) U5.10(TXRXP_D)
GPIO_PD10: J14.24 ; also on sheet 8
GPIO_PE6: C94.1 J14.44 R164.2 SW3.2(B1) SW3.4(B2)
GPIO_PF3: J7.54 J19.26(~{CE1}/GPIO7)
GPIO_PH15: J14.38 ; also on sheet 8
GPIO_PI0: J14.36 ; also on sheet 8
GPIO_PI1: J14.34 ; also on sheet 8
GPIO_PI4: J14.22 ; also on sheet 8
I2C1_SCL: J7.31 J19.28(ID_SC) ; also on sheet 9
I2C1_SDA: J7.33 J19.27(ID_SD) ; also on sheet 9
I2C2_SCL: J10.31 ; also on sheet 9
I2C2_SDA: J10.33 ; also on sheet 9
I2C4_SCL: J14.18 J19.5(GPIO3/SCL1) R55.2 ; also on sheet 8
I2C4_SDA: J14.50 J19.3(GPIO2/SDA1) R54.2 ; also on sheet 8
I2S2_CK: J14.2 J19.12(GPIO18)
I2S2_SDI: J14.32 J19.38(GPIO20)
I2S2_SDO: J14.6 J19.40(GPIO21)
I2S2_WS: J14.4 J19.35(GPIO19)
ISET: R105.1 U5.48(ISET)
LED_MODE: C80.1 R94.1 R95.2 U5.41(CLK125_NDO)
LPO_32k: J10.49 R38.2 R39.2
MDC: R73.2 U5.36(MDC)
MDIO: R84.2 U5.37(MDIO)
MOC1: J14.67 ; also on sheet 9
MOC2: J7.44 J19.7(GPIO4/GCKL)
NRST: C1.1 D1.1 J7.49 Q1.1(G) R2.2 R128.1 SW1.2(B1) SW1.4(B2) ; also on sheet 8
OTG_FS_DM: J10.3 ; also on sheet 6
OTG_FS_DP: J10.1 ; also on sheet 6
OTG_FS_ID: J14.12 ; also on sheet 6
OTG_VBUS: J10.7 ; also on sheet 6
PONKEYN: C102.1 J7.45 SW2.2(B1) SW2.4(B2)
QSPI_BK2_IO0: J10.19 J19.18(GEN5/GPIO24)
QSPI_BK2_IO1: J10.21 J19.22(GEN6/GPIO25)
QSPI_BK2_IO2: J10.23 J19.37(GPIO26)
QSPI_BK2_IO3: J10.25 J19.13(GPIO27/GEN2)
QSPI_BK2_NCS: J14.52 J19.16(GEN4/GPIO23)
QSPI_CLK: J14.66 J19.15(GPIO22/GEN3)
RGMII1_RCLK: R61.2 R70.1 U5.35(RX_CLK)
RGMII1_RCTL: R53.2 R60.1 R66.1 U5.33(RX_DV)
RGMII1_RD0: R59.2 R69.1 U5.32(RXD0)
RGMII1_RD1: R58.2 R68.1 U5.31(RXD1)
RGMII1_RD2: R57.2 R64.1 U5.28(RXD2)
RGMII1_RD3: R56.2 R65.1 U5.27(RXD3)
RGMII1_TCLK: C20.1 R48.2 U5.24(GTX_CLK)
RGMII1_TCTL: R41.2 U5.25(TX_EN)
RGMII1_TD0: R46.2 U5.19(TXD0)
RGMII1_TD1: R45.2 U5.20(TXD1)
RGMII1_TD2: R44.2 U5.21(TXD2)
RGMII1_TD3: R43.2 U5.22(TXD3)
SAI2_FSAm: J10.16 ; also on sheet 9
SAI2_MCLKA: J10.20 ; also on sheet 9
SAI2_SCKAm: J10.14 ; also on sheet 9
SAI2_SDAm: J10.18 ; also on sheet 9
SAI2_SDBm: J10.22 ; also on sheet 9
SD_CD: D12.1 J21.10(CD) R143.2 R146.2
SD_CLK: C14.1 D5.1 J21.5(CLOCK) R37.2 R81.2
SD_CMD: D13.1 J21.3(CMD) R153.2 R154.2
SD_DAT0: D6.1 J21.7(DAT0) R82.2 R83.2
SD_DAT1: D7.1 J21.8(DAT1) R92.2 R93.2
SD_DAT2: D15.1 J21.1(DAT2) R141.2 R142.2
SD_DAT3: D14.1 J21.2(CD/DAT3) R155.2 R156.2
SDMMC1_CD: J10.40 R143.1
SDMMC1_CK: C11.1 J10.38 R37.1
SDMMC1_CMD: J10.36 R154.1
SDMMC1_D0: J10.28 R83.1
SDMMC1_D1: J10.30 R93.1
SDMMC1_D2: J10.32 R142.1
SDMMC1_D3: J10.34 R156.1
SDMMC3_CLK: J10.69 R26.1
SDMMC3_CMD: J10.67 R25.1
SDMMC3_D0: J10.59 R27.1
SDMMC3_D1: J10.61 R28.1
SDMMC3_D2: J10.63 R23.1
SDMMC3_D3: J10.65 R24.1
SPI5_CLK: J10.45 J19.23(GPIO11/SCLK)
SPI5_MISO: J10.43 J19.21(GPIO9/MISO)
SPI5_MOSI: J10.41 J19.19(GPIO10/MOSI)
SPI5_NSS: J10.17 J19.24(~{CE0}/GPIO8)
STLINK_SWCLK: J7.53 ; also on sheet 8
STLINK_SWDIO: J7.51 ; also on sheet 8
SW: C36.1 L3.1 U9.6(SW)
TIM1_CH4: J14.46 J19.31(GPIO6)
TIM4_CH3: J7.35 J19.32(GPIO12)
TIM4_CH4: J7.37 J19.33(GPIO13)
TIM5_CH4: J14.20 J19.29(GPIO5)
UART4_RX: J10.27 ; also on sheet 8
UART4_TX: J7.56 ; also on sheet 8
USART1_CTS: J10.55 R79.1
USART1_RTS: J10.57 R76.1
USART1_RX: J10.53 R78.1
USART1_TX: J10.51 R77.1
USART2_CTS: J14.48 J19.36(GPIO16)
USART2_RTS: J7.48 J19.11(GPIO17/GEN0)
USART2_RX: J10.2 J19.10(RXD0/GPIO15)
USART2_TX: J10.4 J19.8(TXD0/GPIO14)
USB1_EN: J14.42 ; also on sheet 6
USB1_N: J7.62 ; also on sheet 6
USB1_OC: J14.40 ; also on sheet 6
USB1_P: J7.64 ; also on sheet 6
USB2_EN: J7.52 ; also on sheet 6
USB2_N: J7.68 ; also on sheet 6
USB2_OC: J7.50 ; also on sheet 6
USB2_P: J7.70 ; also on sheet 6
VETH1_AVDDH: C52.1 C57.1 C59.1 FB10.2 Q6.3(SOURCE) R103.1 U5.1(AVDDH) U5.12(AVDDH_2) U5.47(AVDDH_3)
VETH1_AVDDL: C55.1 C58.1 R109.2 U5.4(AVDDL_1) U5.9(AVDDL_2)
VETH1_AVDDL_PLL: C41.1 C42.1 C43.1 FB9.2 U5.44(AVDDL_PLL)
VETH1_AVDDL_PMOS: C31.1 FB6.1 FB9.1 Q6.2(DRAIN1) Q6.4(DRAIN2) R109.1
VETH1_DVDDH: C30.1 C34.1 C62.1 D10.2(C) R62.2 R64.2 R65.2 R66.2 R68.2 R69.2 R70.2 R74.1 R85.1 R89.1 R94.2 R102.1 R104.1 R106.2 R107.2 R108.1 U5.16(DVDDH_1) U5.34(DVDDH_2) U5.40(DVDDH_3) U8.5(VCC)
VETH1_DVDDL: C32.1 C33.1 FB6.2 U5.14(DVDDL_1) U5.18(DVDDL_2) U5.23(DVDDL_3) U5.26(DVDDL_4) U5.30(DVDDL_5) U5.39(DVDDL_6)
WL_HOST_WAKE: J14.28 R19.2 U3.13(WL_HOST_WAKE)
WL_REG_ON: J14.30 R133.1
N303234: J13.11(GRL+) R104.2
N303238: J13.14(YEL+) R102.2
N303440: C51.2 R100.2 U5.46(XI) X3.1
N303536: C47.2 R100.1 U5.45(XO) X3.3
N303624: C48.1 J13.5(CT1) J13.6(CT2) R103.2
N303732: R128.2 R129.2 U8.2(A)
N3772447: TP6.1(TP) U3.28(PCM_SYNC)
N3772513: TP5.1(TP) U3.27(PCM_IN)
N3772517: TP9.1(TP) U3.26(PCM_CLK)
N3772521: TP8.1(TP) U3.25(PCM_OUT)
N3772562: TP7.1(TP) U3.4(FM_RX)
N3774700: C9.1 R30.2 X1.1
N3775644: R49.2 R51.2 U3.2(WL_BT_ANT)
N3776012: R22.2 R133.2 U3.12(WL_REG_ON)
N3776054: R23.2 R31.1 U3.14(SDIO_DATA_2)
N3776279: R24.2 R32.1 U3.15(SDIO_DATA_3)
N3776286: R25.2 R33.1 U3.16(SDIO_DATA_CMD)
N3776293: R26.2 R34.1 U3.17(SDIO_DATA_CLK)
N3776300: R27.2 R35.1 U3.18(SDIO_DATA_0)
N3776307: R28.2 R36.1 U3.19(SDIO_DATA_1)
N3776951: R38.1 U3.24(LPO)
N3777387: R42.1 U3.29(NC_2)
N3779189: C22.1 R51.1 R52.2
N3779193: C21.1 J16.1(CENTER) R52.1
N3780208: ANT1.1(FEED) C23.1 R50.1
N3780222: C24.1 R49.1 R50.2
N3787372: J7.55 TP2.1(TP)
N3787386: J7.57 TP15.1(TP)
N3787400: J7.59 TP1.1(TP)
N3793884: L1.1 U3.21(VIN_LDO_OUT)
N3794135: C49.1 L1.2 U3.23(VIN_LDO)
N3820313: C26.1 C27.1 C29.1 R63.2 R67.2 U4.2(VIN)
N3820535: C44.1 C46.1 C63.1 L2.2 R75.1 R99.1 U4.5(OUT)
N3820638: R71.1 R75.2 U4.7(FB)
N3911606: R167.1 SW3.1(A1) SW3.3(A2)
N3915722: Q3.3(D) R3.1 R5.1
N3915999: Q2.3(D) R7.1 R8.1
N3917680: J9.2(COM1) R15.2
N3973979: J9.5(COM2) R16.1
N3987111: LED1.1(A) R1.2
N3987115: Q1.3(D) R1.1
N3990987: R67.1 R160.2 R161.1 U4.8(EN)
N3991147: C19.1 TP4.1(TP) U4.1(PG)
N3991771: L2.1 U4.3(SW)
N4522056: Q9.3(D) R11.2 R12.1
N4540513: R115.1 U9.4(BST)
N4540517: C36.2 R115.2
N4540641: R127.2 U9.3(EN/SYNC)
N4540827: C40.1 C45.1 C50.1 C53.1 L3.2 R136.1 R139.1
N4540887: C54.1 R138.1 U9.2(VCC)
N4540895: R138.2 U9.8(PG)
N4541105: R144.1 U9.1(FB)
N4541109: R139.2 R144.2 R147.1
N4563547: Q7.2(S) R150.2 R151.1
N4563559: Q7.3(D) Q8.3(D)

Not connected (* = marked no-connect by the designer): J7 11* 13* 15* 17* 18* 19* 20* 21* 22* 23* 24* 26* 28* 29* 30* 32* 34* 38* 39* 40* 41* 43* 63* 65* 67* 69*; J10 5* 11* 13* 15* 24* 35* 37* 39*; J13 17(NC1)* 18(NC2)*; J14 8* 10* 16* 26* 41* 54* 62* 64* 68* 70*; J17 3*; J21 11(GND1)* 12(GND2)* 15(GND5)* 16(GND6)*; U3 5(NC)* 8(NC_1)* 30(NC_3)* 32(NC_4)* 35(NC_5)* 37(GPIO4)* 38(GPIO3)* 39(GPIO2)* 40(GPIO1)* 45(TP1)* 46(TP2)* 47(TP3)*; U8 1(NC)*

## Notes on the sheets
sheet 1
- Strapping Options:
- 3.3V
- 1.2V
- Pin35
- PHY Address:
- Pin15
- ( 0 0 ) 1 1 1
- Pin17
- Pin27
- MODE:
- 1 1 1 1
- RGMII MODE
- Pin28
- 10/100/1000 Speed
  Half/Full Duplex
- Pin31
- Pin32
- Layout Note:
- Enable CLK125
- The RGMII1 signals must be length-matched by TX and RX groups:
  That is, the TX group should be matched within 300 Mil (7.62 mm),
  and the RX group should be matched within 300 Mil (7.62 mm).
  Total length should not exceed 1750 Mil (44.5 mm).
  There is no requirement to match the TX and RX groups because their clocks are not related.
- CLK125_EN:
- Pin33
- 0 (Default)
- Disable CLK125
- Dis 125MHz Output
- 1.2V
- Review Note:
- LED_MODE:
- Pin41
- 1
- The KSZ9031RNX reduces board cost and
  simplifies board layout by using on-chip
  termination resistors for the four differential pairs,
   so no other resistors be needed.
- Single-LED Mode
- Layout Note:
- Place R* Close To MPU.
- Layout Note:
- Max trace-length mismatch
  between GBE signals pairs
  should be no greater than ? mm.
- 100 ohms differential trace
  impedance.
- Layout Note:
- Place R* Close To PHY.
- 3.3V
- 1.2V
- IO=3.3V
- 1.2V
- ETH1_INTn
sheet 2
- Input Current:2A
- Output Current:3A
- Output Current:3A
- Output Current:3A
- Vgate=(EXT_VIN)/(R9+R8)*R8
       =(12~24V)/(100K+78K)*78K
       =5.28V~10.57V
- Output Current:2A
- Vout=Vref*(1+R98/R97)
          =0.6V*(1+180k/40.2k)
          =0.6V*5.5
          =3.3V
sheet 3
- Layout Note:
- Layout Note:
- Half-Duplex Master
- The RGMII signals must be length-matched
- by RX,TX and MDC groups
- Differential impedance:90 Ohm
- GPIO_PI11
- QSPI_BK1_NCS
- HDMI_CEC
- HDMI_INT
- QSPI_BK1_IO0
- HDMI_NRST
- QSPI_BK1_IO1
- QSPI_BK1_IO2
- LTDC_B7
- QSPI_BK1_IO3
- I2C4_SCL
- LTDC_B6
- QSPI_BK2_IO0
- LTDC_B4
- LTDC_B5
- GPIO_PG9
- DVP_D12
- QSPI_BK2_IO1
- QSPI_BK2_IO2
- LTDC_B3
- Layout Note:
- QSPI_BK2_IO3
- Grove Digital Interface
- LTDC_B2
- SAI2_SDBm
- The SDMMC1 signals must be length-matched
- QSPI_CLK
- LTDC_B1
- LTDC_B0
- LTDC_G6
- LTDC_G7
- DVP_D8
- SPI1_MOSI
- LTDC_G5
- SPI1_MISO
- User LEDs
- LTDC_G4
- DVP_D11
- GPIO_PI3
- DVP_D10
- SPI1_CLK
- LTDC_G3
- FDCAN1_RX
- LTDC_G2
- FDCAN1_TX
- ETH_CLK
- DVP_D9
- LTDC_G1
- LTDC_G0
- LTDC_R7
- LTDC_R6
- LTDC_R5
- LTDC_R4
- DAC1_OUT2
- WiFi/BLE Interface
- LTDC_R3
- Layout Note:
- LTDC_R1
- LTDC_R2
- Differential impedance:100 Ohm
- LTDC_R0
- LTDC_CLK
- DVP_D13
- SPI1_NSS
- LTDC_DE
- LTDC_HSYNC
- LTDC_VSYNC
- GPIO_PE12
- Layout Note:
- Layout Note:
- The SDMMC3 signals must be length-matched
- The DCMI signals must be length-matched
- VDD
- VBUS_OTG
- BST_OUT
- 1V8_AUDIO
- VBUS_SW
- 1V2_HDMI
- 3V3_HDMI
- VREF+
- ADC2_INP2
- ADC1_INN1
- ADC1_INP1
- PWR_ON
- PMIC_WAKEUP
- GPIO_PZ4
- PA0_WKUP
- GPIO_PD4
- GPIO_PF12
- GPIO_PF8
- USB1_OC
- GPIO_PG11
- SPI5_MISO
- USB1_EN
- GPIO_PG3
- FDCAN2_RX
- FDCAN2_TX
- I2C6_SDA
- FDCAN1_RX
- I2C6_SCL
- FDCAN1_TX
- Layout Note:
- Differential impedance:90 Ohm
sheet 4
- RPI Interface
- MicroSD CARD
- Layout Note:
- Place C52 R80 C53 Close To MPU.
- Backup PWR
- PWR_WAKEUP
- USER_BUT
- Internal pull-up
- RST_BUT
- VBAT:1.2V~3.6V
- RST_LED
- BOOT Mode
- SD CARD
- eMMC
- Truth Table
- BOOT2
- BOOT1
- BOOT0
- eMMC
- 0
- 1
- 0
- SD
- 1
- 0
- 1
sheet 5
- NC
- NC
- NC
- Layout Note：Current 1A
- Note：change TXC to Hosonic
